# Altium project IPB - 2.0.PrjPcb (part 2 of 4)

## Sheet Mezzanine_Conn.SchDoc: MARS2 - IPB - Mezzanine Connector
size 431 x 279 mm; Organization: ORGANIZATION; Address1: APPLIED PHYSICS LAB; Address2: UNIVERSITY OF WASHINGTON; Address3: 1013 NE 40TH STREET; Address4: SEATTLE, WA 98105; Revision: -; SheetNumber: 3; SheetTotal: 23; ENG_APP_DATE: --/--/--; DSN_APP_DATE: --/--/--; CHK_APP_DATE: --/--/--
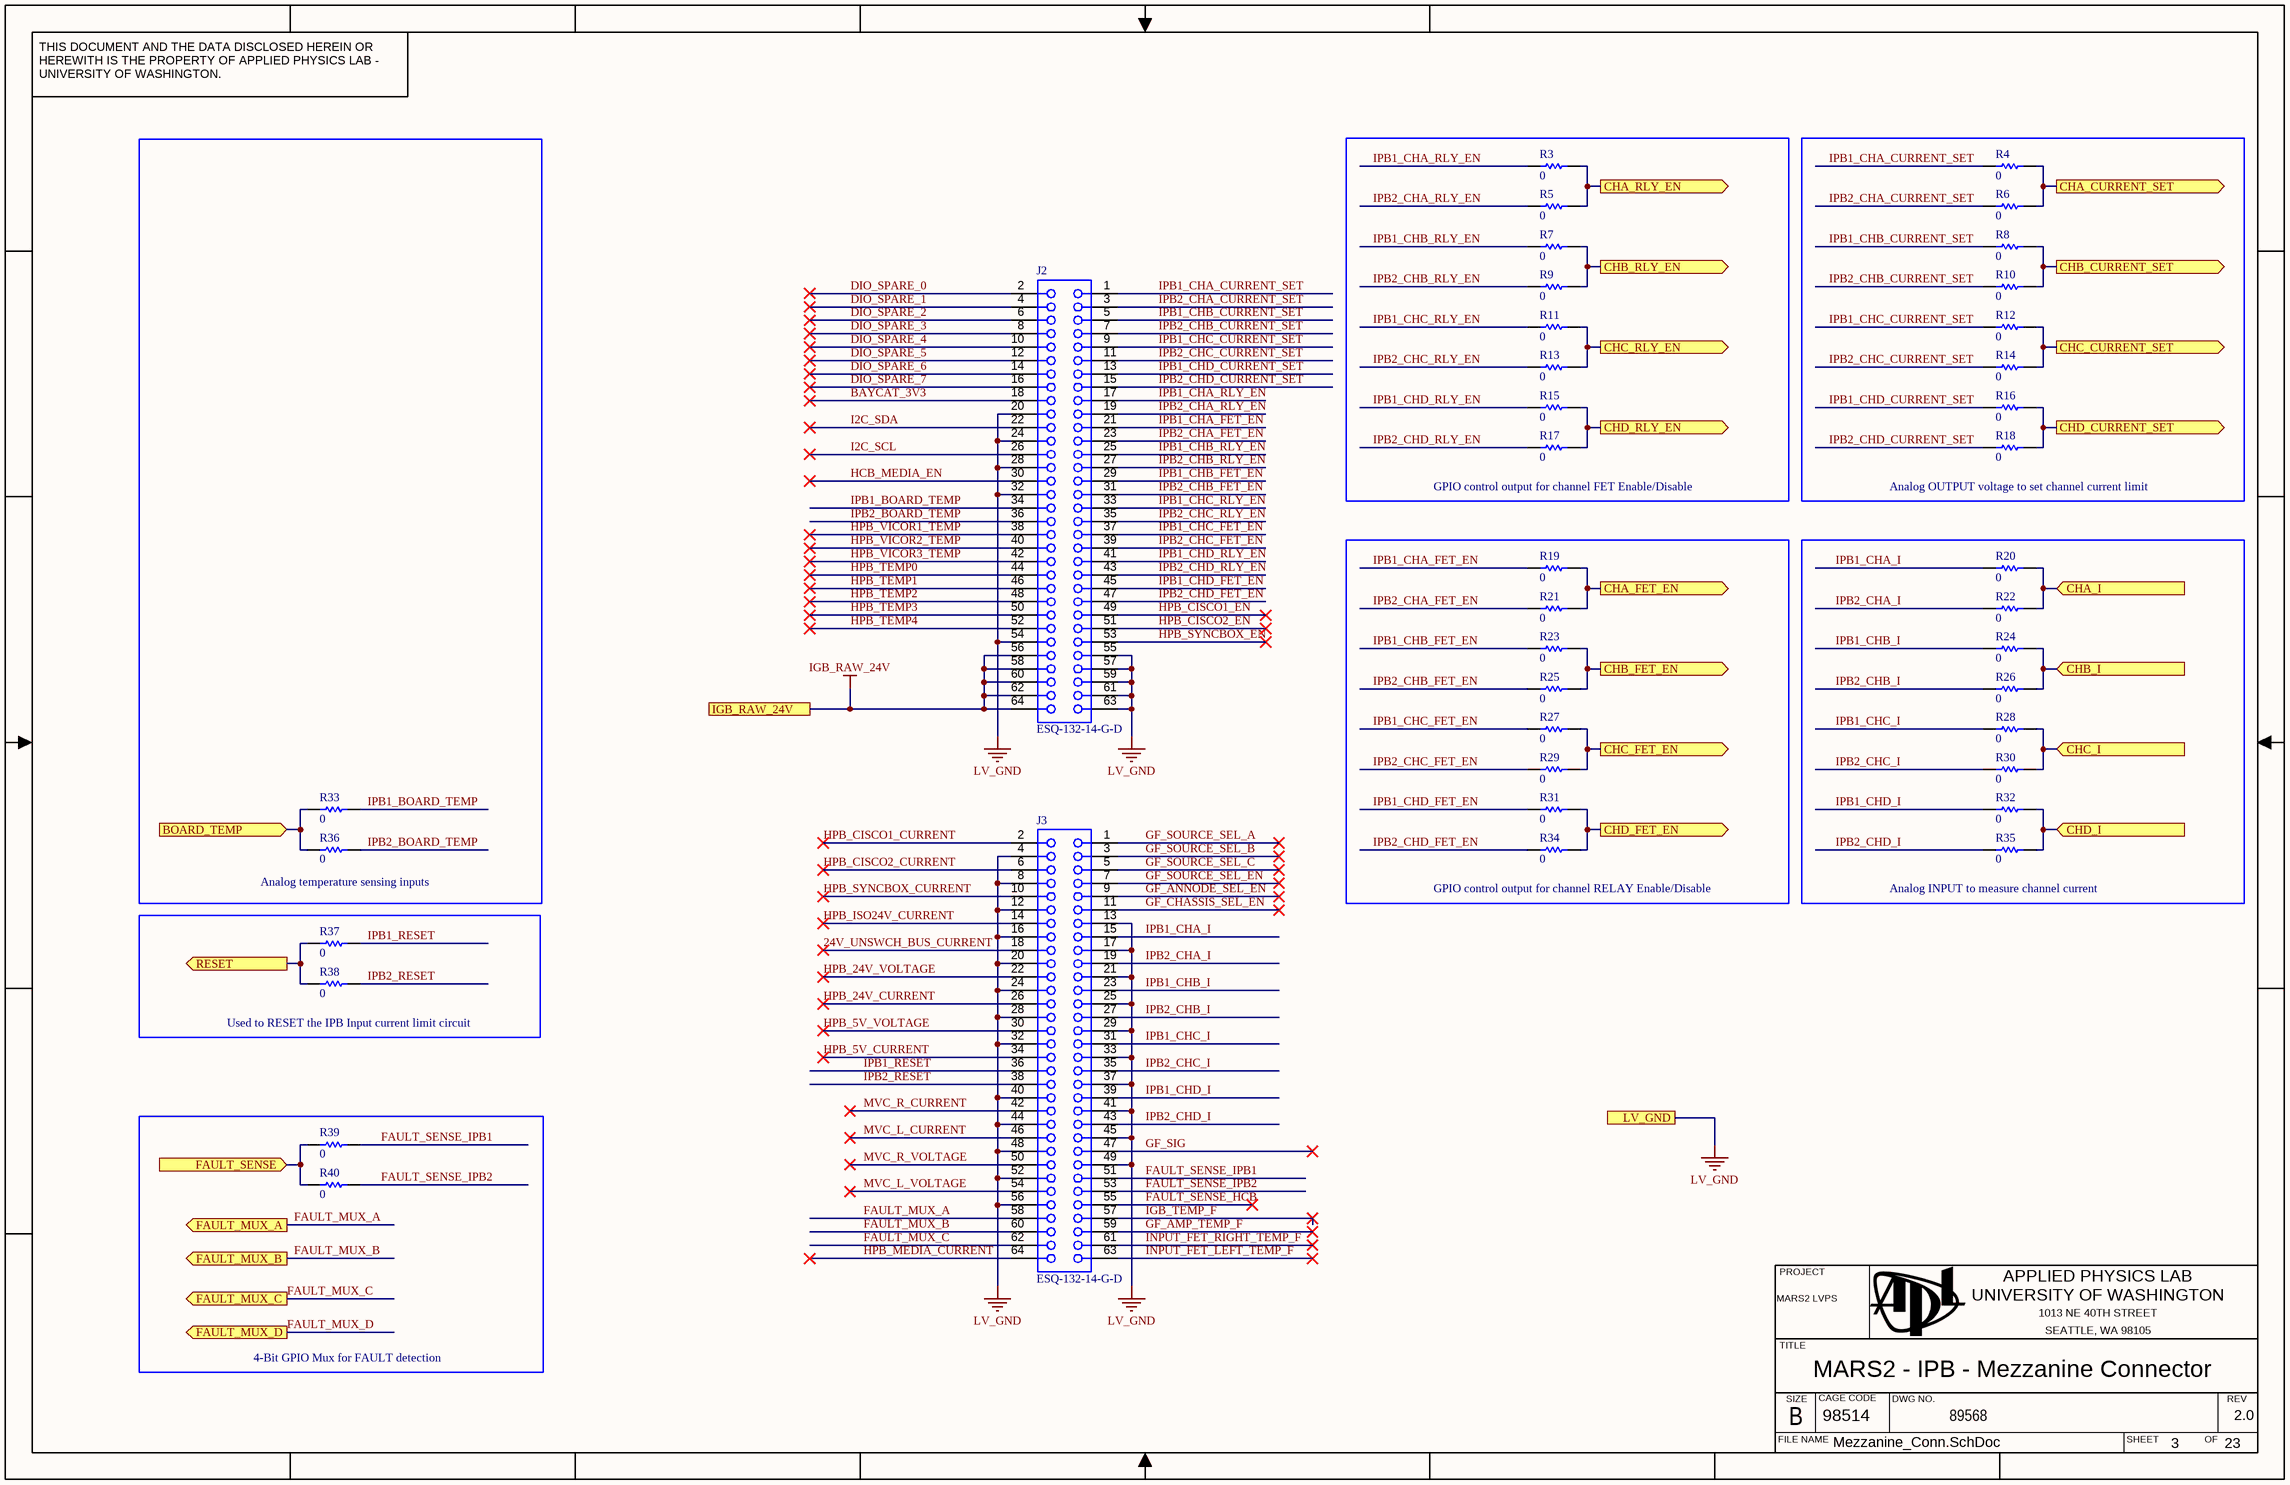
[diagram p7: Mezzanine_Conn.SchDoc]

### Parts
J2  ESQ-132-14-G-D  [SMTC-ESQ-132-14-X-D]
J3  ESQ-132-14-G-D  [SMTC-ESQ-132-14-X-D]
R3  value 0  [RESC2013X60X35ML10T20]  (hidden comment: Resistor 0R +/- 5% 0805 125 mW)
R4  value 0  [RESC2013X60X35ML10T20]  (hidden comment: Resistor 0R +/- 5% 0805 125 mW)
R5  value 0  [RESC2013X60X35ML10T20]  (hidden comment: Resistor 0R +/- 5% 0805 125 mW)
R6  value 0  [RESC2013X60X35ML10T20]  (hidden comment: Resistor 0R +/- 5% 0805 125 mW)
R7  value 0  [RESC2013X60X35ML10T20]  (hidden comment: Resistor 0R +/- 5% 0805 125 mW)
R8  value 0  [RESC2013X60X35ML10T20]  (hidden comment: Resistor 0R +/- 5% 0805 125 mW)
R9  value 0  [RESC2013X60X35ML10T20]  (hidden comment: Resistor 0R +/- 5% 0805 125 mW)
R10  value 0  [RESC2013X60X35ML10T20]  (hidden comment: Resistor 0R +/- 5% 0805 125 mW)
R11  value 0  [RESC2013X60X35ML10T20]  (hidden comment: Resistor 0R +/- 5% 0805 125 mW)
R12  value 0  [RESC2013X60X35ML10T20]  (hidden comment: Resistor 0R +/- 5% 0805 125 mW)
R13  value 0  [RESC2013X60X35ML10T20]  (hidden comment: Resistor 0R +/- 5% 0805 125 mW)
R14  value 0  [RESC2013X60X35ML10T20]  (hidden comment: Resistor 0R +/- 5% 0805 125 mW)
R15  value 0  [RESC2013X60X35ML10T20]  (hidden comment: Resistor 0R +/- 5% 0805 125 mW)
R16  value 0  [RESC2013X60X35ML10T20]  (hidden comment: Resistor 0R +/- 5% 0805 125 mW)
R17  value 0  [RESC2013X60X35ML10T20]  (hidden comment: Resistor 0R +/- 5% 0805 125 mW)
R18  value 0  [RESC2013X60X35ML10T20]  (hidden comment: Resistor 0R +/- 5% 0805 125 mW)
R19  value 0  [RESC2013X60X35ML10T20]  (hidden comment: Resistor 0R +/- 5% 0805 125 mW)
R20  value 0  [RESC2013X60X35ML10T20]  (hidden comment: Resistor 0R +/- 5% 0805 125 mW)
R21  value 0  [RESC2013X60X35ML10T20]  (hidden comment: Resistor 0R +/- 5% 0805 125 mW)
R22  value 0  [RESC2013X60X35ML10T20]  (hidden comment: Resistor 0R +/- 5% 0805 125 mW)
R23  value 0  [RESC2013X60X35ML10T20]  (hidden comment: Resistor 0R +/- 5% 0805 125 mW)
R24  value 0  [RESC2013X60X35ML10T20]  (hidden comment: Resistor 0R +/- 5% 0805 125 mW)
R25  value 0  [RESC2013X60X35ML10T20]  (hidden comment: Resistor 0R +/- 5% 0805 125 mW)
R26  value 0  [RESC2013X60X35ML10T20]  (hidden comment: Resistor 0R +/- 5% 0805 125 mW)
R27  value 0  [RESC2013X60X35ML10T20]  (hidden comment: Resistor 0R +/- 5% 0805 125 mW)
R28  value 0  [RESC2013X60X35ML10T20]  (hidden comment: Resistor 0R +/- 5% 0805 125 mW)
R29  value 0  [RESC2013X60X35ML10T20]  (hidden comment: Resistor 0R +/- 5% 0805 125 mW)
R30  value 0  [RESC2013X60X35ML10T20]  (hidden comment: Resistor 0R +/- 5% 0805 125 mW)
R31  value 0  [RESC2013X60X35ML10T20]  (hidden comment: Resistor 0R +/- 5% 0805 125 mW)
R32  value 0  [RESC2013X60X35ML10T20]  (hidden comment: Resistor 0R +/- 5% 0805 125 mW)
R33  value 0  [RESC2013X60X35ML10T20]  (hidden comment: Resistor 0R +/- 5% 0805 125 mW)
R34  value 0  [RESC2013X60X35ML10T20]  (hidden comment: Resistor 0R +/- 5% 0805 125 mW)
R35  value 0  [RESC2013X60X35ML10T20]  (hidden comment: Resistor 0R +/- 5% 0805 125 mW)
R36  value 0  [RESC2013X60X35ML10T20]  (hidden comment: Resistor 0R +/- 5% 0805 125 mW)
R37  value 0  [RESC2013X60X35ML10T20]  (hidden comment: Resistor 0R +/- 5% 0805 125 mW)
R38  value 0  [RESC2013X60X35ML10T20]  (hidden comment: Resistor 0R +/- 5% 0805 125 mW)
R39  value 0  [RESC2013X60X35ML10T20]  (hidden comment: Resistor 0R +/- 5% 0805 125 mW)
R40  value 0  [RESC2013X60X35ML10T20]  (hidden comment: Resistor 0R +/- 5% 0805 125 mW)

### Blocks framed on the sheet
Analog temperature sensing inputs: R33 R36
GPIO control output for channel FET Enable/Disable: R3 R5 R7 R9 R11 R13 R15 R17
Analog OUTPUT voltage to set channel current limit: R4 R6 R8 R10 R12 R14 R16 R18
GPIO control output for channel RELAY Enable/Disable: R19 R21 R23 R25 R27 R29 R31 R34
Analog INPUT to measure channel current: R20 R22 R24 R26 R28 R30 R32 R35
Used to RESET the IPB Input current limit circuit: R37 R38
4-Bit GPIO Mux for FAULT detection: R39 R40

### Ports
BOARD_TEMP (in), CHA_CURRENT_SET (out), CHA_FET_EN (out), CHA_I (in), CHA_RLY_EN (out), CHB_CURRENT_SET (out), CHB_FET_EN (out), CHB_I (in), CHB_RLY_EN (out), CHC_CURRENT_SET (out), CHC_FET_EN (out), CHC_I (in), CHC_RLY_EN (out), CHD_CURRENT_SET (out), CHD_FET_EN (out), CHD_I (in), CHD_RLY_EN (out), FAULT_MUX_A (out), FAULT_MUX_B (out), FAULT_MUX_C (out), FAULT_MUX_D (out), FAULT_SENSE (in), IGB_RAW_24V, LV_GND, RESET (out)

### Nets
IGB_RAW_24V: J2.56 J2.58 J2.60 J2.62 J2.64 ; port IGB_RAW_24V  [project net LV_IGB_P24V]
LV_GND: J2.20 J2.24 J2.28 J2.32 J2.54 J2.55 J2.57 J2.59 J2.61 J2.63 J3.4 J3.8 J3.12 J3.13 J3.16 J3.17 J3.20 J3.21 J3.24 J3.25 J3.28 J3.29 J3.32 J3.33 J3.37 J3.40 J3.41 J3.44 J3.45 J3.48 J3.49 J3.52 J3.56 ; port LV_GND
24V_UNSWCH_BUS_CURRENT: J3.18  [project net 24V_UNSWCH_BUS_CURRENT_3]
BAYCAT_3V3: J2.18  [project net BAYCAT_3V3_3]
BOARD_TEMP: R33.1 R36.1 ; port BOARD_TEMP
CHA_CURRENT_SET: R4.1 R6.1 ; port CHA_CURRENT_SET
CHA_FET_EN: R19.1 R21.1 ; port CHA_FET_EN
CHA_I: R20.1 R22.1 ; port CHA_I
CHA_RLY_EN: R3.1 R5.1 ; port CHA_RLY_EN
CHB_CURRENT_SET: R8.1 R10.1 ; port CHB_CURRENT_SET
CHB_FET_EN: R23.1 R25.1 ; port CHB_FET_EN
CHB_I: R24.1 R26.1 ; port CHB_I
CHB_RLY_EN: R7.1 R9.1 ; port CHB_RLY_EN
CHC_CURRENT_SET: R12.1 R14.1 ; port CHC_CURRENT_SET
CHC_FET_EN: R27.1 R29.1 ; port CHC_FET_EN
CHC_I: R28.1 R30.1 ; port CHC_I
CHC_RLY_EN: R11.1 R13.1 ; port CHC_RLY_EN
CHD_CURRENT_SET: R16.1 R18.1 ; port CHD_CURRENT_SET
CHD_FET_EN: R31.1 R34.1 ; port CHD_FET_EN
CHD_I: R32.1 R35.1 ; port CHD_I
CHD_RLY_EN: R15.1 R17.1 ; port CHD_RLY_EN
DIO_SPARE_0: J2.2  [project net DIO_SPARE_0_3]
DIO_SPARE_1: J2.4  [project net DIO_SPARE_1_3]
DIO_SPARE_2: J2.6  [project net DIO_SPARE_2_3]
DIO_SPARE_3: J2.8  [project net DIO_SPARE_3_3]
DIO_SPARE_4: J2.10  [project net DIO_SPARE_4_3]
DIO_SPARE_5: J2.12  [project net DIO_SPARE_5_3]
DIO_SPARE_6: J2.14  [project net DIO_SPARE_6_3]
DIO_SPARE_7: J2.16  [project net DIO_SPARE_7_3]
FAULT_MUX_A: J3.58 ; port FAULT_MUX_A
FAULT_MUX_B: J3.60 ; port FAULT_MUX_B
FAULT_MUX_C: J3.62 ; port FAULT_MUX_C
FAULT_SENSE: R39.1 R40.1 ; port FAULT_SENSE
FAULT_SENSE_HCB: J3.55  [project net FAULT_SENSE_HCB_3]
FAULT_SENSE_IPB1: J3.51 R39.2  [project net FAULT_SENSE_IPB1_3]
FAULT_SENSE_IPB2: J3.53 R40.2  [project net FAULT_SENSE_IPB2_3]
GF_AMP_TEMP_F: J3.59  [project net GF_AMP_TEMP_F_3]
GF_ANNODE_SEL_EN: J3.9  [project net GF_ANNODE_SEL_EN_3]
GF_CHASSIS_SEL_EN: J3.11  [project net GF_CHASSIS_SEL_EN_3]
GF_SIG: J3.47  [project net GF_SIG_3]
GF_SOURCE_SEL_A: J3.1  [project net GF_SOURCE_SEL_A_3]
GF_SOURCE_SEL_B: J3.3  [project net GF_SOURCE_SEL_B_3]
GF_SOURCE_SEL_C: J3.5  [project net GF_SOURCE_SEL_C_3]
GF_SOURCE_SEL_EN: J3.7  [project net GF_SOURCE_SEL_EN_3]
HCB_MEDIA_EN: J2.30  [project net HCB_MEDIA_EN_3]
HPB_5V_CURRENT: J3.34  [project net HPB_5V_CURRENT_3]
HPB_5V_VOLTAGE: J3.30  [project net HPB_5V_VOLTAGE_3]
HPB_24V_CURRENT: J3.26  [project net HPB_24V_CURRENT_3]
HPB_24V_VOLTAGE: J3.22  [project net HPB_24V_VOLTAGE_3]
HPB_CISCO1_CURRENT: J3.2  [project net HPB_CISCO1_CURRENT_3]
HPB_CISCO1_EN: J2.49  [project net HPB_CISCO1_EN_3]
HPB_CISCO2_CURRENT: J3.6  [project net HPB_CISCO2_CURRENT_3]
HPB_CISCO2_EN: J2.51  [project net HPB_CISCO2_EN_3]
HPB_ISO24V_CURRENT: J3.14  [project net HPB_ISO24V_CURRENT_3]
HPB_MEDIA_CURRENT: J3.64  [project net HPB_MEDIA_CURRENT_3]
HPB_SYNCBOX_CURRENT: J3.10  [project net HPB_SYNCBOX_CURRENT_3]
HPB_SYNCBOX_EN: J2.53  [project net HPB_SYNCBOX_EN_3]
HPB_TEMP0: J2.44  [project net HPB_TEMP0_3]
HPB_TEMP1: J2.46  [project net HPB_TEMP1_3]
HPB_TEMP2: J2.48  [project net HPB_TEMP2_3]
HPB_TEMP3: J2.50  [project net HPB_TEMP3_3]
HPB_TEMP4: J2.52  [project net HPB_TEMP4_3]
HPB_VICOR1_TEMP: J2.38  [project net HPB_VICOR1_TEMP_3]
HPB_VICOR2_TEMP: J2.40  [project net HPB_VICOR2_TEMP_3]
HPB_VICOR3_TEMP: J2.42  [project net HPB_VICOR3_TEMP_3]
I2C_SCL: J2.26  [project net I2C_SCL_3]
I2C_SDA: J2.22  [project net I2C_SDA_3]
IGB_TEMP_F: J3.57  [project net IGB_TEMP_F_3]
INPUT-FAULT-RESET: R37.1 R38.1 ; port RESET
INPUT_FET_LEFT_TEMP_F: J3.63  [project net INPUT_FET_LEFT_TEMP_F_3]
INPUT_FET_RIGHT_TEMP_F: J3.61  [project net INPUT_FET_RIGHT_TEMP_F_3]
IPB1_BOARD_TEMP: J2.34 R33.2  [project net IPB1_BOARD_TEMP_3]
IPB1_CHA_CURRENT_SET: J2.1 R4.2  [project net IPB1_CHA_CURRENT_SET_3]
IPB1_CHA_FET_EN: J2.21 R19.2  [project net IPB1_CHA_FET_EN_3]
IPB1_CHA_I: J3.15 R20.2  [project net IPB1_CHA_I_3]
IPB1_CHA_RLY_EN: J2.17 R3.2  [project net IPB1_CHA_RLY_EN_3]
IPB1_CHB_CURRENT_SET: J2.5 R8.2  [project net IPB1_CHB_CURRENT_SET_3]
IPB1_CHB_FET_EN: J2.29 R23.2  [project net IPB1_CHB_FET_EN_3]
IPB1_CHB_I: J3.23 R24.2  [project net IPB1_CHB_I_3]
IPB1_CHB_RLY_EN: J2.25 R7.2  [project net IPB1_CHB_RLY_EN_3]
IPB1_CHC_CURRENT_SET: J2.9 R12.2  [project net IPB1_CHC_CURRENT_SET_3]
IPB1_CHC_FET_EN: J2.37 R27.2  [project net IPB1_CHC_FET_EN_3]
IPB1_CHC_I: J3.31 R28.2  [project net IPB1_CHC_I_3]
IPB1_CHC_RLY_EN: J2.33 R11.2  [project net IPB1_CHC_RLY_EN_3]
IPB1_CHD_CURRENT_SET: J2.13 R16.2  [project net IPB1_CHD_CURRENT_SET_3]
IPB1_CHD_FET_EN: J2.45 R31.2  [project net IPB1_CHD_FET_EN_3]
IPB1_CHD_I: J3.39 R32.2  [project net IPB1_CHD_I_3]
IPB1_CHD_RLY_EN: J2.41 R15.2  [project net IPB1_CHD_RLY_EN_3]
IPB1_RESET: J3.36 R37.2  [project net IPB1_RESET_3]
IPB2_BOARD_TEMP: J2.36 R36.2  [project net IPB2_BOARD_TEMP_3]
IPB2_CHA_CURRENT_SET: J2.3 R6.2  [project net IPB2_CHA_CURRENT_SET_3]
IPB2_CHA_FET_EN: J2.23 R21.2  [project net IPB2_CHA_FET_EN_3]
IPB2_CHA_I: J3.19 R22.2  [project net IPB2_CHA_I_3]
IPB2_CHA_RLY_EN: J2.19 R5.2  [project net IPB2_CHA_RLY_EN_3]
IPB2_CHB_CURRENT_SET: J2.7 R10.2  [project net IPB2_CHB_CURRENT_SET_3]
IPB2_CHB_FET_EN: J2.31 R25.2  [project net IPB2_CHB_FET_EN_3]
IPB2_CHB_I: J3.27 R26.2  [project net IPB2_CHB_I_3]
IPB2_CHB_RLY_EN: J2.27 R9.2  [project net IPB2_CHB_RLY_EN_3]
IPB2_CHC_CURRENT_SET: J2.11 R14.2  [project net IPB2_CHC_CURRENT_SET_3]
IPB2_CHC_FET_EN: J2.39 R29.2  [project net IPB2_CHC_FET_EN_3]
IPB2_CHC_I: J3.35 R30.2  [project net IPB2_CHC_I_3]
IPB2_CHC_RLY_EN: J2.35 R13.2  [project net IPB2_CHC_RLY_EN_3]
IPB2_CHD_CURRENT_SET: J2.15 R18.2  [project net IPB2_CHD_CURRENT_SET_3]
IPB2_CHD_FET_EN: J2.47 R34.2  [project net IPB2_CHD_FET_EN_3]
IPB2_CHD_I: J3.43 R35.2  [project net IPB2_CHD_I_3]
IPB2_CHD_RLY_EN: J2.43 R17.2  [project net IPB2_CHD_RLY_EN_3]
IPB2_RESET: J3.38 R38.2  [project net IPB2_RESET_3]
MVC_L_CURRENT: J3.46  [project net MVC_L_CURRENT_3]
MVC_L_VOLTAGE: J3.54  [project net MVC_L_VOLTAGE_3]
MVC_R_CURRENT: J3.42  [project net MVC_R_CURRENT_3]
MVC_R_VOLTAGE: J3.50  [project net MVC_R_VOLTAGE_3]

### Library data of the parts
J2 J3 = CMP-002-00093-5: Conn Elevated Socket SKT 64 POS 2.54mm Solder ST Top Entry Thru-Hole Tube; Manufacturer: Samtec; Voltage Rating (AC): 550V; Current Rating: 6.9A; Number of Contacts: 64; Row Spacing: 0.1inch; Connector Type: Receptacle; Contact Resistance: 10mR
R3-R40 = CMP-009-00007-7: Chip Resistor, 0 Ohm, 0.125 W, -55 to 155 degC, 0805 (2012 Metric); Power: 125mW; Voltage Rating: 50V

## Sheet External_Interface_Conn.SchDoc: MARS2 - IPB - Instrument Channel Conn
size 431 x 279 mm; Organization: ORGANIZATION; Address1: APPLIED PHYSICS LAB; Address2: UNIVERSITY OF WASHINGTON; Address3: 1013 NE 40TH STREET; Address4: SEATTLE, WA 98105; Revision: -; SheetNumber: 9; SheetTotal: 23; ENG_APP_DATE: --/--/--; DSN_APP_DATE: --/--/--; CHK_APP_DATE: --/--/--
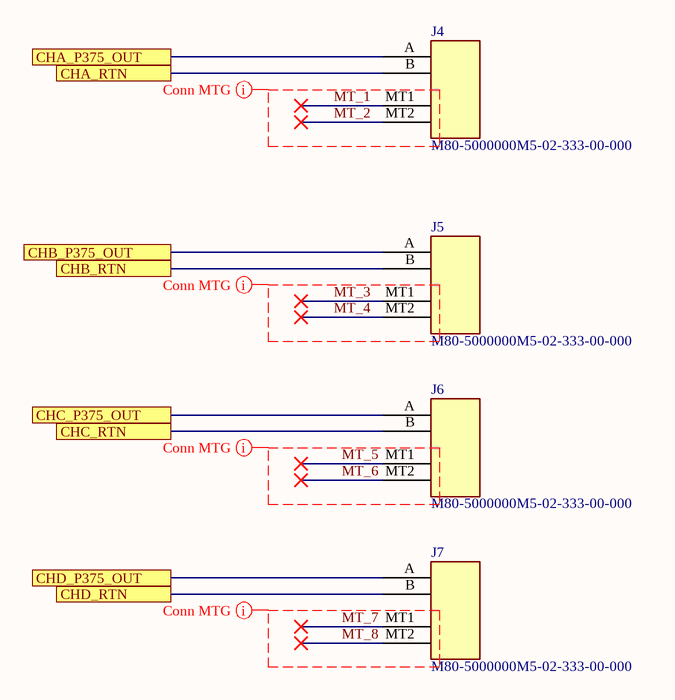
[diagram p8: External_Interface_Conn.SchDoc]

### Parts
J4  M80-5000000M5-02-333-00-000  [FP-M80-5000000M5-02-333-0-MFG]
J5  M80-5000000M5-02-333-00-000  [FP-M80-5000000M5-02-333-0-MFG]
J6  M80-5000000M5-02-333-00-000  [FP-M80-5000000M5-02-333-0-MFG]
J7  M80-5000000M5-02-333-00-000  [FP-M80-5000000M5-02-333-0-MFG]

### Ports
CHA_P375_OUT, CHA_RTN, CHB_P375_OUT, CHB_RTN, CHC_P375_OUT, CHC_RTN, CHD_P375_OUT, CHD_RTN

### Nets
MT_1: J4.MT1(MNT_1)  [project net MT_1_9]
MT_2: J4.MT2(MNT_2)  [project net MT_2_9]
MT_3: J5.MT1(MNT_1)  [project net MT_3_9]
MT_4: J5.MT2(MNT_2)  [project net MT_4_9]
MT_5: J6.MT1(MNT_1)  [project net MT_5_9]
MT_6: J6.MT2(MNT_2)  [project net MT_6_9]
MT_7: J7.MT1(MNT_1)  [project net MT_7_9]
MT_8: J7.MT2(MNT_2)  [project net MT_8_9]
NetD1_A_1: J4.B ; port CHA_RTN
NetD1_A_4: J4.A ; port CHA_P375_OUT
NetD1_B_1: J5.B ; port CHB_RTN
NetD1_B_4: J5.A ; port CHB_P375_OUT
NetD1_C_1: J6.B ; port CHC_RTN
NetD1_C_4: J6.A ; port CHC_P375_OUT
NetD1_D_1: J7.B ; port CHD_RTN
NetD1_D_4: J7.A ; port CHD_P375_OUT

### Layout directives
net class Mounting Hole: MT_1, MT_2, MT_3, MT_4, MT_5, MT_6, MT_7, MT_8

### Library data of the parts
J4-J7 = CMP-002-00075-7: Conn Header R/a 2POS 4MM; Manufacturer: Harwin; Number of Positions: 2; Pitch: 4.00mm; Current Rating: 40A; Contact Resistance: 25mR; Voltage Rating: 800V; Gender: Male; Insulation Resistance: 100MR

## Sheet Fault_Sensing.SchDoc: MARS2 - IPB - Fault Multiplexing
size 431 x 279 mm; Organization: ORGANIZATION; Address1: APPLIED PHYSICS LAB; Address2: UNIVERSITY OF WASHINGTON; Address3: 1013 NE 40TH STREET; Address4: SEATTLE, WA 98105; Revision: -; SheetNumber: 10; SheetTotal: 23; ENG_APP_DATE: --/--/--; DSN_APP_DATE: --/--/--; CHK_APP_DATE: --/--/--
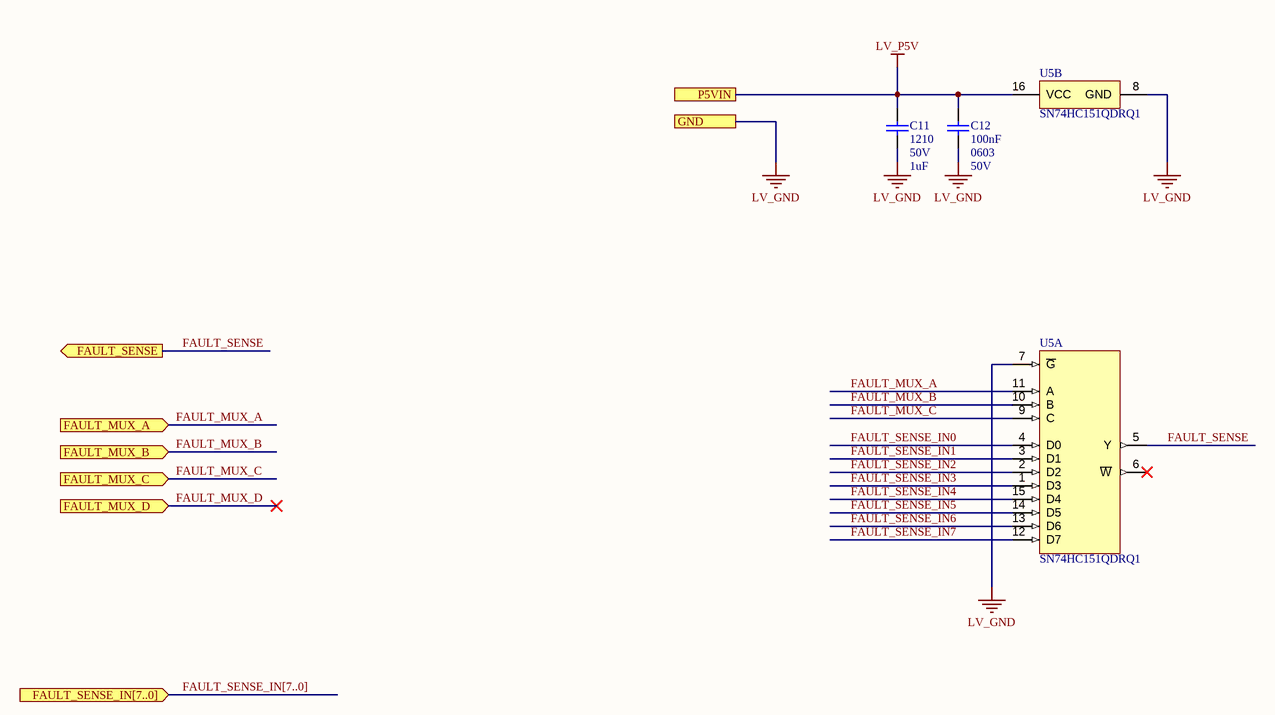
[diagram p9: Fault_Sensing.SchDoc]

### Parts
C11  value 1uF  Case/Package: 1210  Voltage Rating: 50V  [CAPC3225X270X30ML30]  (hidden comment: Capacitor 1uF 10%, 50V, X7R, 1210)
C12  value 100nF  Case/Package: 0603  Voltage Rating: 50V  [CAPC1608X90X40ML10T20]  (hidden comment: Capacitor 100nF +/- 10%, 50V, X7R, 0603)
U5  SN74HC151QDRQ1  [D0016A_M]  (parts A,B of 2)

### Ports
FAULT_MUX_A (in), FAULT_MUX_B (in), FAULT_MUX_C (in), FAULT_MUX_D (in), FAULT_SENSE (out), FAULT_SENSE_IN[7..0] (in), GND, P5VIN

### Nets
LV_GND: C11.2 C12.1 U5.7(~{G}) U5.8(GND) ; port GND
LV_P5V: C11.1 C12.2 U5.16(VCC) ; port P5VIN
FAULT_MUX_A: U5.11(A) ; port FAULT_MUX_A
FAULT_MUX_B: U5.10(B) ; port FAULT_MUX_B
FAULT_MUX_C: U5.9(C) ; port FAULT_MUX_C
FAULT_SENSE: U5.5(Y) ; port FAULT_SENSE
FAULT_SENSE_IN0: U5.4(D0)
FAULT_SENSE_IN1: U5.3(D1)
FAULT_SENSE_IN2: U5.2(D2)
FAULT_SENSE_IN3: U5.1(D3)
FAULT_SENSE_IN4: U5.15(D4)
FAULT_SENSE_IN5: U5.14(D5)
FAULT_SENSE_IN6: U5.13(D6)
FAULT_SENSE_IN7: U5.12(D7)

Not connected (* = marked no-connect by the designer): U5 6(~{W})*

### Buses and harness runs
bus FAULT_SENSE_IN[7..0] = port FAULT_SENSE_IN[7..0]

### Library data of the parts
C11 = CMP-001-00181-10: Chip Capacitor, 1uF, 10%, 50 V, X7R 1210 (3225 Metric); Capacitor Type: Ceramic
C12 = CMP-001-00206-10: Chip Capacitor, 100nF, +/- 10%, 50 V, X7R 0603 (1608 Metric); Capacitor Type: Ceramic
U5 = CMP-016-00018-2: Automotive 5-V, 8: 1 1-channel general-purpose multiplexer 16-SOIC -40 to 125; Max Supply Voltage: 6V; Bandwidth: 28MHz; Min Supply Voltage: 2V; Number of Output Lines: 1; Number of Input Lines: 8; High Level Output Current: 7.8mA; Logic Function: Multiplexer,Mux; Propagation Delay: 33ns

## Sheet Local_Power_Supplies.SchDoc: MARS2 - IPB - Local Power Supplies
size 431 x 279 mm; Organization: ORGANIZATION; Address1: APPLIED PHYSICS LAB; Address2: UNIVERSITY OF WASHINGTON; Address3: 1013 NE 40TH STREET; Address4: SEATTLE, WA 98105; Revision: -; SheetNumber: 11; SheetTotal: 23; ENG_APP_DATE: --/--/--; DSN_APP_DATE: --/--/--; CHK_APP_DATE: --/--/--
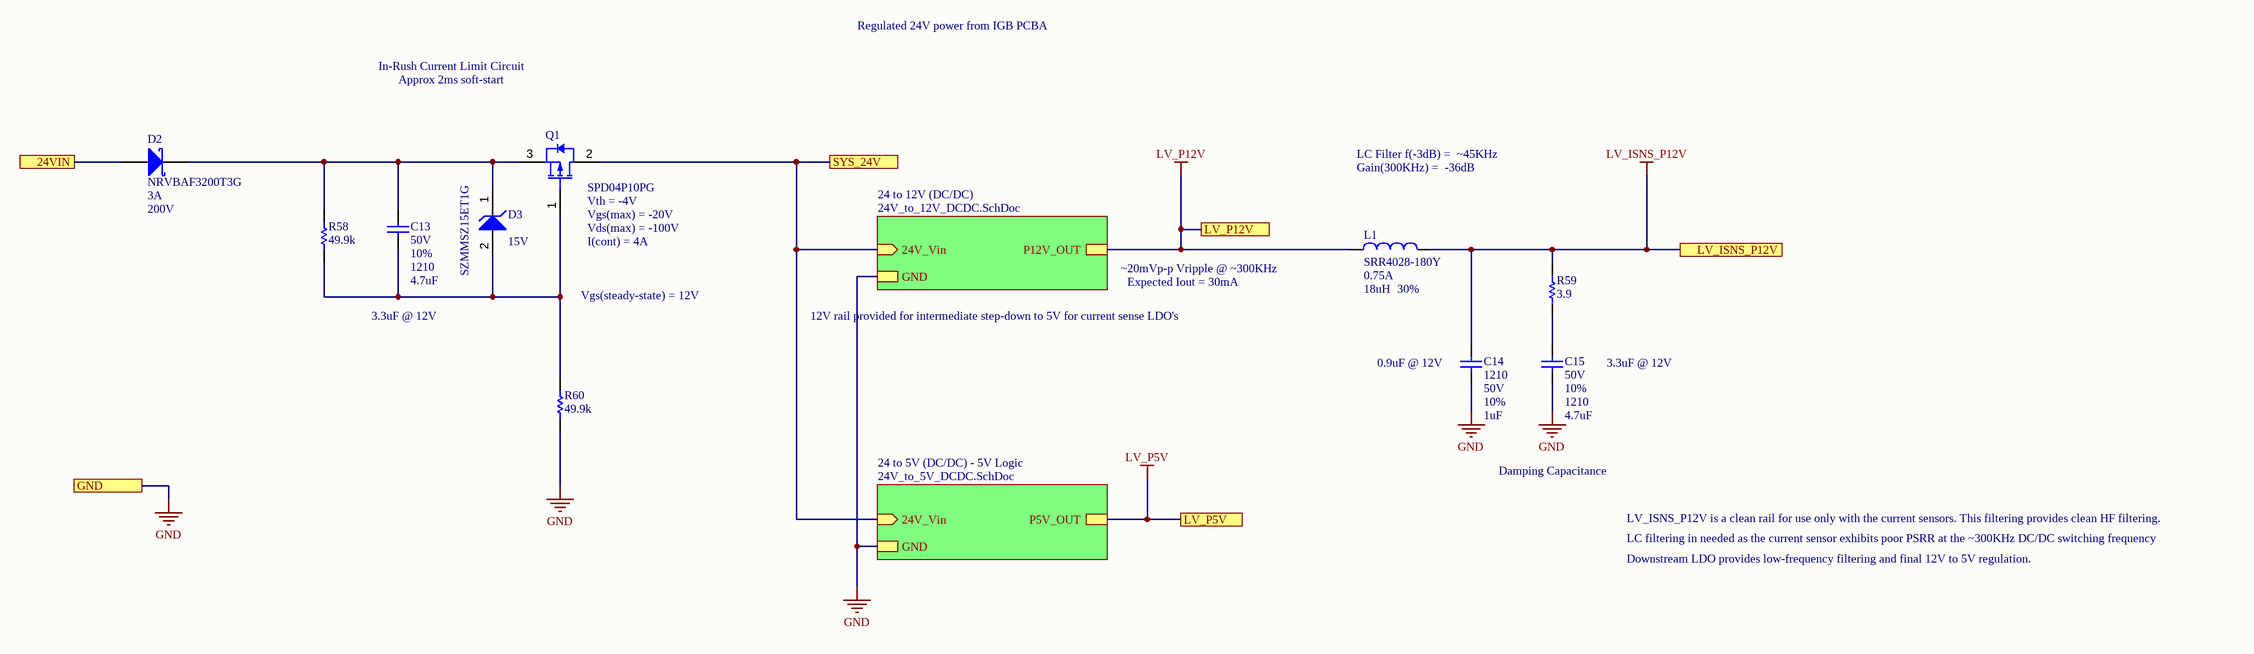
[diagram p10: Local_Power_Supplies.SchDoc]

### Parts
C13  value 4.7uF  Voltage Rating: 50V  Tolerance: 10%  Case/Package: 1210  [CAPC3225X270X30ML30]  (hidden comment: Capacitor 4.7uF 10%, 50V, X7R, 1210)
C14  value 1uF  Case/Package: 1210  Voltage Rating: 50V  Tolerance: 10%  [CAPC3225X270X30ML30]  (hidden comment: Capacitor 1uF 10%, 50V, X7R, 1210)
C15  value 4.7uF  Voltage Rating: 50V  Tolerance: 10%  Case/Package: 1210  [CAPC3225X270X30ML30]  (hidden comment: Capacitor 4.7uF 10%, 50V, X7R, 1210)
D2  NRVBAF3200T3G  Average Rectified Current: 3A  Max Reverse Voltage (DC): 200V  [DIOM4326X11M]
D3  SZMMSZ15ET1G  Zener Voltage: 15V  [ONSC-SOD-123-2-425-04_V]
L1  SRR4028-180Y  Inductance Tolerance: 30%  Saturation Current: 0.75A  Inductance: 18uH  [INDP4848X30M]
Q1  SPD04P10PG  [INF-PG-TO252-3-1_M]
R58  value 49.9k  [RESC1608X55X25ML10T15]  (hidden comment: Resistor 49K9 +/-1% 0603 100 mW)
R59  value 3.9  [RESC1609X50X30ML08T20]  (hidden comment: Resistor 3R9 +/-1% 0603 100 mW)
R60  value 49.9k  [RESC1608X55X25ML10T15]  (hidden comment: Resistor 49K9 +/-1% 0603 100 mW)

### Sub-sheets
24 to 5V (DC/DC) - 5V Logic = 24V_to_5V_DCDC.SchDoc: 24V_Vin (in), P5V_OUT, GND
24 to 12V (DC/DC) = 24V_to_12V_DCDC.SchDoc: 24V_Vin (in), P12V_OUT, GND

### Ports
24VIN, GND, LV_ISNS_P12V, LV_P5V, LV_P12V, SYS_24V

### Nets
COIL_DRV_HIGH: Q1.2(DRAIN) ; port SYS_24V, sheet 24 to 12V (DC/DC)/24V_Vin, sheet 24 to 5V (DC/DC) - 5V Logic/24V_Vin
GND: C14.2 C15.2 R60.1 ; port GND, sheet 24 to 12V (DC/DC)/GND, sheet 24 to 5V (DC/DC) - 5V Logic/GND  [project net LV_GND]
LV_IGB_P24V: D2.1(A) ; port 24VIN
LV_ISNS_P12V: C14.1 L1.2 R59.2 ; port LV_ISNS_P12V
LV_P5V: port LV_P5V, sheet 24 to 5V (DC/DC) - 5V Logic/P5V_OUT
LV_P12V: L1.1 ; port LV_P12V, sheet 24 to 12V (DC/DC)/P12V_OUT
NetC13_1: C13.1 D3.2(A) Q1.1(GATE) R58.1 R60.2
NetC13_2: C13.2 D2.2(K) D3.1(K) Q1.3(SOURCE) R58.2
NetC15_1: C15.1 R59.1

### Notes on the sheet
- Regulated 24V power from IGB PCBA
- In-Rush Current Limit Circuit
- Approx 2ms soft-start
- LC Filter f(-3dB) =  ~45KHz
- Gain(300KHz) =  -36dB
- (near Q1) Vgs(max) = -20V
- (near Q1) Vds(max) = -100V
- (near Q1) I(cont) = 4A
- (near Q1) Vth = -4V
- 3.3uF @ 12V
- Vgs(steady-state) = 12V
- 12V rail provided for intermediate step-down to 5V for current sense LDO's
- |0mVp-p Vripple @ ~300KHz
- Expected Iout = 30mA
- (near C14) 0.9uF @ 12V
- Damping Capacitance
- LV_ISNS_P12V is a clean rail for use only with the current sensors. This filtering provides clean HF filtering.
- Downstream LDO provides low-frequency filtering and final 12V to 5V regulation.
- LC filtering in needed as the current sensor exhibits poor PSRR at the ~300KHz DC/DC switching frequency

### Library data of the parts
C13 C15 = CMP-001-00183-10: Chip Capacitor, 4.7uF, 10%, 50 V, X7R 1210 (3225 Metric); Capacitor Type: Ceramic; Decade: 1uF
C14 = CMP-001-00181-10: as C11 on sheet Fault_Sensing
D2 = CMP-004-00041-1: Diode Schottky Barrier Rectifier 200V 3A 2-Pin SMA-FL T/R
D3 = CMP-004-00039-2: Diode Zener Single 15V 5% 500mW Automotive 2-Pin SOD-123 T/R; Max Reverse Leakage Current: 50nA
L1 = CMP-006-00041-3: Inductor Power Shielded Wirewound 18uH 30% 11.64 Q-Factor Ferrite 0.75A Saturation 160mROhm DCR; Manufacturer: Bourns; Q Factor: 11.64; Self Resonant Frequency: 25MHz; Current Rating: 0.98A; Decade: 10uH; DC Resistance (DCR): 160mR
Q1 = CMP-013-00049-3: Trans MOSFET P-CH 100V 4A Automotive 3-Pin(2+Tab) TO-252 T/R; Input Capacitance: 319pF; Drain to Source Breakdown Voltage: -100V; Rds On Max: 1R; Power Dissipation: 38W; Gate to Source Voltage (Vgs): 20V; Transistor Type: PMOS
R58 R60 = CMP-009-01001-4: Chip Resistor, 49.9k Ohm, +/- 1%, 0.1 W, -55 to 155 degC, 0603 (1608 Metric); Power: 100mW; Voltage Rating: 75V; Decade: 10k
R59 = CMP-009-01177-2: Chip Resistor, 3.9 Ohm, +/- 1%, 0.1 W, -55 to 155 degC, 0603 (1608 Metric); Voltage Rating: SEE DATASHEET; Power: 100mW; Decade: 1

## Sheet 24V_to_12V_DCDC.SchDoc: MARS2 - IPB - 24V to 12V DC/DC
size 431 x 279 mm; SheetNumber: 13; SheetTotal: 23; ENG_APP_DATE: --/--/--; DSN_APP_DATE: --/--/--; CHK_APP_DATE: --/--/--
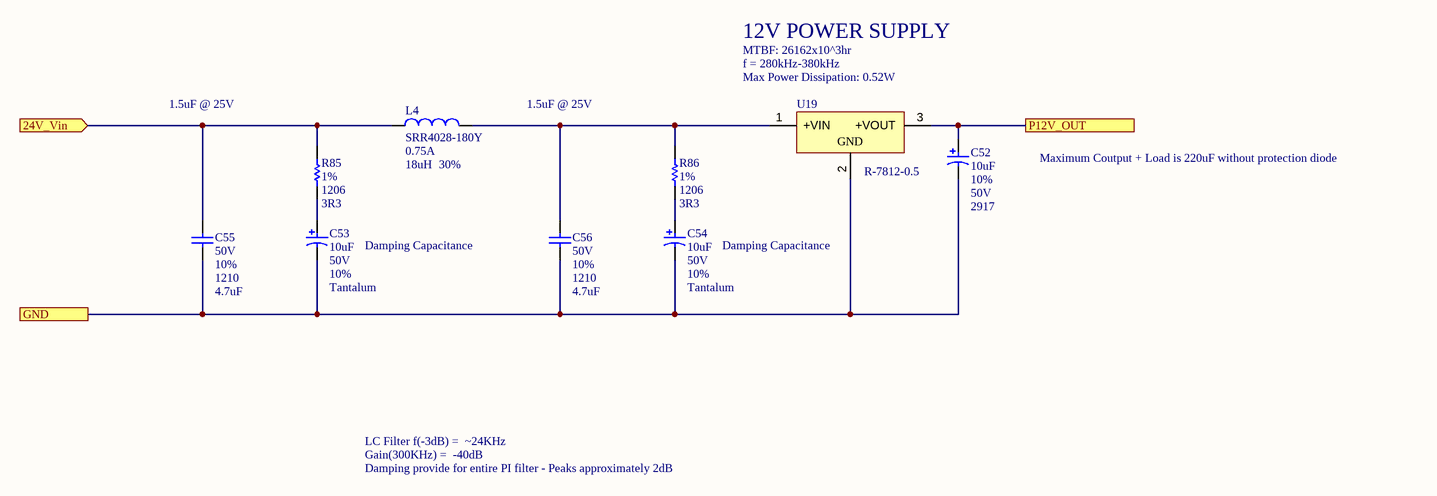
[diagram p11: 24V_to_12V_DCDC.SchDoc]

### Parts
C52  value 10uF  Tolerance: 10%  Voltage Rating: 50V  Case/Package: 2917  [KEMT-D-7343-31-2_L]  (hidden comment: T491D106K050AT)
C53  value 10uF  Voltage: 50V  Tolerance: 10%  Dielectric Material: Tantalum  [KEMT-D-7343-31-2_L]  (hidden comment: T491D106K050AT)
C54  value 10uF  Voltage: 50V  Tolerance: 10%  Dielectric Material: Tantalum  [KEMT-D-7343-31-2_L]  (hidden comment: T491D106K050AT)
C55  value 4.7uF  Voltage Rating: 50V  Tolerance: 10%  Case/Package: 1210  [CAPC3225X270X30ML30]  (hidden comment: Capacitor 4.7uF 10%, 50V, X7R, 1210)
C56  value 4.7uF  Voltage Rating: 50V  Tolerance: 10%  Case/Package: 1210  [CAPC3225X270X30ML30]  (hidden comment: Capacitor 4.7uF 10%, 50V, X7R, 1210)
L4  SRR4028-180Y  Inductance Tolerance: 30%  Saturation Current: 0.75A  Inductance: 18uH  [INDP4848X30M]
R85  value 3R3  Tolerance: 1%  Case/Package: 1206  [RESC3115X07M]  (hidden comment: Res Thick Film 1206 3.3 Ohm 1% 0.5W ±200ppm/°C Molded SMD Punched Carrier T/R)
R86  value 3R3  Tolerance: 1%  Case/Package: 1206  [RESC3115X07M]  (hidden comment: Res Thick Film 1206 3.3 Ohm 1% 0.5W ±200ppm/°C Molded SMD Punched Carrier T/R)
U19  R-7812-0.5  [REPO-R-78XX-3_V]

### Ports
24V_Vin (in), GND, P12V_OUT

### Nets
COIL_DRV_HIGH: C55.2 L4.1 R85.2 ; port 24V_Vin
LV_GND: C52.2 C53.2 C54.2 C55.1 C56.1 U19.2(GND) ; port GND
LV_P12V: C52.1 U19.3(+VOUT) ; port P12V_OUT
NetC53_1: C53.1 R85.1
NetC54_1: C54.1 R86.1
NetC56_2: C56.2 L4.2 R86.2 U19.1(+VIN)

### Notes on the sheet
- 12V POWER SUPPLY
- MTBF: 26162x10^3hr
- f = 280kHz-380kHz
- (near U19) Max Power Dissipation: 0.52W
- 1.5uF @ 25V
- Maximum Coutput + Load is 220uF without protection diode
- Damping Capacitance
- LC Filter f(-3dB) =  |4KHz
- Gain(300KHz) =  -40dB
- Damping provide for entire PI filter - Peaks approximately 2dB

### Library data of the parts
C52-C54 = CMP-001-00088-10: 10uF Solid MnO2 Tantalum Electrolytic Capacitor; 50 V dc +/-10%; T491 Series; Manufacturer: KEMET; Life (Hours): 2000Hour; Dissipation Factor: 6%; Ripple Current: 433mA; Leakage Current: 5uA; ESR (Equivalent Series Resistance): 800mR; Polarity: Polar
C55 C56 = CMP-001-00183-10: as C13 on sheet Local_Power_Supplies
L4 = CMP-006-00041-3: as L1 on sheet Local_Power_Supplies
R85 R86 = CMP-009-01213-6: Chip Resistor, 3.3 Ohm, 1%, 0.5W, ±200ppm/°C, 1206 (3216 Metric); Manufacturer: Panasonic; Power: 500mW; Decade: 1
U19 = CMP-019-00064-2: 0.5A DC/DC-Converter 'INNOLINE' SIP3 reg; V. In: 15-32; V. Out: 12; mA. Out: 500; Current - Output 1: 500mA; Isolation Voltage: 1kV; Min Input Voltage: 15V; Switching Frequency: 380kHz; Efficiency: 97%; Max Input Voltage: 32V; Max Output Voltage: 12V; Max Output Power: 6W; Nominal Input Voltage: 24V; Isolation: Non-Isolated

## Sheet 24V_to_5V_DCDC.SchDoc: MARS2 - IPB - 24V to 5V DC/DC
size 431 x 279 mm; SheetNumber: 12; SheetTotal: 23; ENG_APP_DATE: --/--/--; DSN_APP_DATE: --/--/--; CHK_APP_DATE: --/--/--
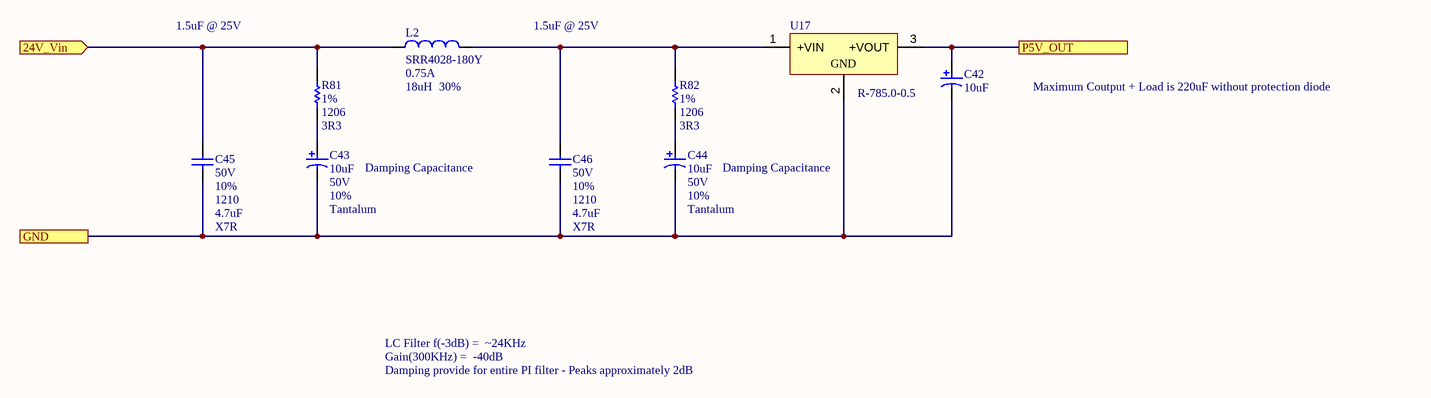
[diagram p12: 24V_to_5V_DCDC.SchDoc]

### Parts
C42  value 10uF  [KEMT-D-7343-31-2_L]  (hidden comment: T491D106K050AT)
C43  value 10uF  Voltage: 50V  Tolerance: 10%  Dielectric Material: Tantalum  [KEMT-D-7343-31-2_L]  (hidden comment: T491D106K050AT)
C44  value 10uF  Voltage: 50V  Tolerance: 10%  Dielectric Material: Tantalum  [KEMT-D-7343-31-2_L]  (hidden comment: T491D106K050AT)
C45  value 4.7uF  Voltage Rating: 50V  Tolerance: 10%  Case/Package: 1210  Dielectric: X7R  [CAPC3225X270X30ML30]  (hidden comment: Capacitor 4.7uF 10%, 50V, X7R, 1210)
C46  value 4.7uF  Voltage Rating: 50V  Tolerance: 10%  Case/Package: 1210  Dielectric: X7R  [CAPC3225X270X30ML30]  (hidden comment: Capacitor 4.7uF 10%, 50V, X7R, 1210)
L2  SRR4028-180Y  Inductance Tolerance: 30%  Saturation Current: 0.75A  Inductance: 18uH  [INDP4848X30M]
R81  value 3R3  Tolerance: 1%  Case/Package: 1206  [RESC3115X07M]  (hidden comment: Res Thick Film 1206 3.3 Ohm 1% 0.5W ±200ppm/°C Molded SMD Punched Carrier T/R)
R82  value 3R3  Tolerance: 1%  Case/Package: 1206  [RESC3115X07M]  (hidden comment: Res Thick Film 1206 3.3 Ohm 1% 0.5W ±200ppm/°C Molded SMD Punched Carrier T/R)
U17  R-785.0-0.5  [REPO-R-78XX-3_V]

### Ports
24V_Vin (in), GND, P5V_OUT

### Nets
COIL_DRV_HIGH: C45.2 L2.1 R81.2 ; port 24V_Vin
LV_GND: C42.2 C43.2 C44.2 C45.1 C46.1 U17.2(GND) ; port GND
LV_P5V: C42.1 U17.3(+VOUT) ; port P5V_OUT
NetC43_1: C43.1 R81.1
NetC44_1: C44.1 R82.1
NetC46_2: C46.2 L2.2 R82.2 U17.1(+VIN)

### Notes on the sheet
- 1.5uF @ 25V
- Maximum Coutput + Load is 220uF without protection diode
- Damping Capacitance
- LC Filter f(-3dB) =  |4KHz
- Gain(300KHz) =  -40dB
- Damping provide for entire PI filter - Peaks approximately 2dB

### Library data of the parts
C42 = CMP-001-00088-10: 10uF Solid MnO2 Tantalum Electrolytic Capacitor; 50 V dc +/-10%; T491 Series; Manufacturer: KEMET; Voltage: 50V; Tolerance: 10%; Life (Hours): 2000Hour; Dissipation Factor: 6%; Ripple Current: 433mA; Leakage Current: 5uA; ESR (Equivalent Series Resistance): 800mR; Polarity: Polar
C43 C44 = CMP-001-00088-10: as C52 on sheet 24V_to_12V_DCDC
C45 C46 = CMP-001-00183-10: as C13 on sheet Local_Power_Supplies
L2 = CMP-006-00041-3: as L1 on sheet Local_Power_Supplies
R81 R82 = CMP-009-01213-6: as R85 on sheet 24V_to_12V_DCDC
U17 = CMP-019-00062-2: 0.5A DC/DC-Converter 'INNOLINE' SIP3 reg; V. In: 6.5-32; V. Out: 5.0; mA. Out: 500; Nominal Input Voltage: 24V; Max Power Dissipation: 3W; Efficiency: 94%; Min Input Voltage (DC): 6.5V; Current - Output 1: 500mA; Isolation: Non-Isolated; Max Input Voltage: 32V; Switching Frequency: 380kHz; Max Output Power: 2.5W; Max Output Voltage: 5V; Isolation Voltage: 2kV

## Sheet Mechanical.SchDoc: MARS2 - IPB - Mechanicals
size 431 x 279 mm; Organization: ORGANIZATION; Address1: APPLIED PHYSICS LAB; Address2: UNIVERSITY OF WASHINGTON; Address3: 1013 NE 40TH STREET; Address4: SEATTLE, WA 98105; Revision: -; SheetNumber: 14; SheetTotal: 23; ENG_APP_DATE: --/--/--; DSN_APP_DATE: --/--/--; CHK_APP_DATE: --/--/--
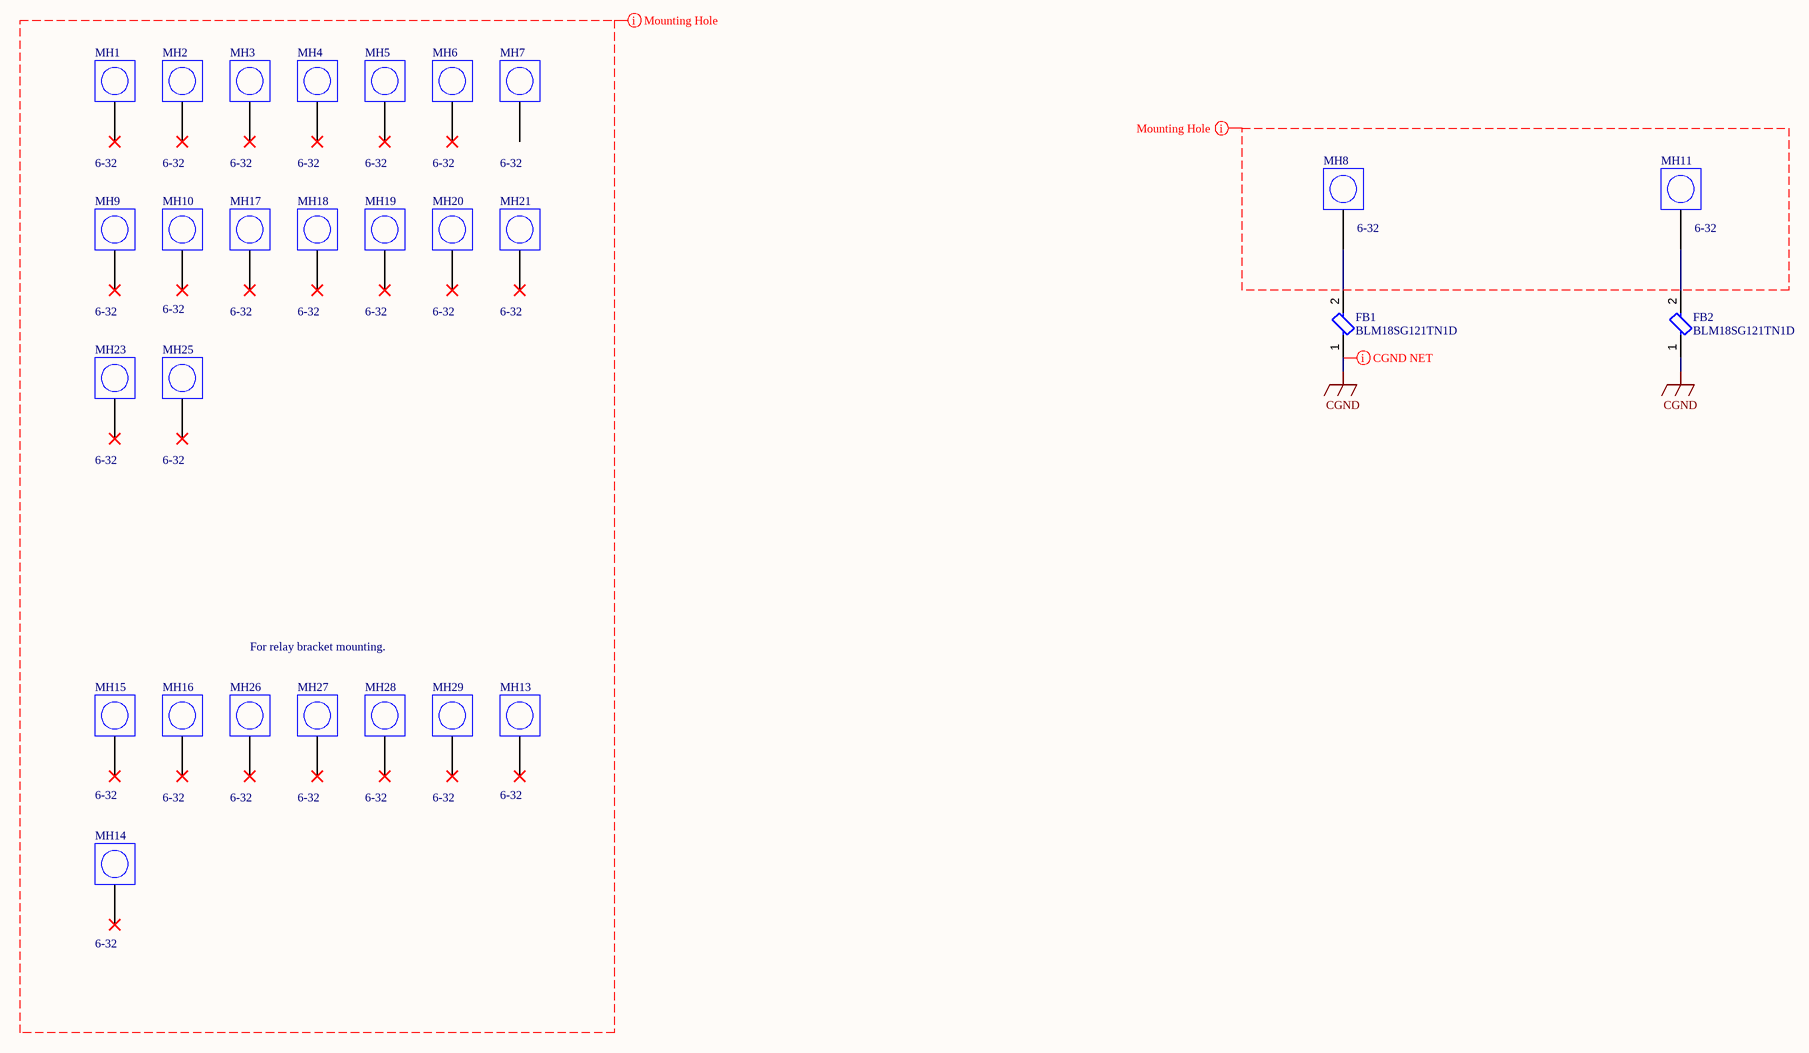
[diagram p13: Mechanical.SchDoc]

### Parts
FB1  BLM18SG121TN1D  [FP-BLM18-0_15-t0_5-d1_2-IPC_B]
FB2  BLM18SG121TN1D  [FP-BLM18-0_15-t0_5-d1_2-IPC_B]
MH1  Fastener Size: 6-32  [MH-M3-Footprint-1 - Oversized MARS2]  (hidden comment: MH-MARS2-6-32)  (no BOM)
MH2  Fastener Size: 6-32  [MH-M3-Footprint-1 - Oversized MARS2]  (hidden comment: MH-MARS2-6-32)  (no BOM)
MH3  Fastener Size: 6-32  [MH-M3-Footprint-1 - Oversized MARS2]  (hidden comment: MH-MARS2-6-32)  (no BOM)
MH4  Fastener Size: 6-32  [MH-M3-Footprint-1 - Oversized MARS2]  (hidden comment: MH-MARS2-6-32)  (no BOM)
MH5  Fastener Size: 6-32  [MH-M3-Footprint-1 - Oversized MARS2]  (hidden comment: MH-MARS2-6-32)  (no BOM)
MH6  Fastener Size: 6-32  [MH-M3-Footprint-1 - Oversized MARS2]  (hidden comment: MH-MARS2-6-32)  (no BOM)
MH7  Fastener Size: 6-32  [MH-M3-Footprint-1 - Oversized MARS2]  (hidden comment: MH-MARS2-6-32)  (no BOM)
MH8  Fastener Size: 6-32  [MH-M3-Footprint-1 - Oversized MARS2]  (hidden comment: MH-MARS2-6-32)  (no BOM)
MH9  Fastener Size: 6-32  [MH-M3-Footprint-1 - Oversized MARS2]  (hidden comment: MH-MARS2-6-32)  (no BOM)
MH10  Fastener Size: 6-32  [MH-M3-Footprint-1 - Oversized MARS2]  (hidden comment: MH-MARS2-6-32)  (no BOM)
MH11  Fastener Size: 6-32  [MH-M3-Footprint-1 - Oversized MARS2]  (hidden comment: MH-MARS2-6-32)  (no BOM)
MH13  Fastener Size: 6-32  [MH-M3-Footprint-1 - Oversized MARS2]  (hidden comment: MH-MARS2-6-32)  (no BOM)
MH14  Fastener Size: 6-32  [MH-M3-Footprint-1 - Oversized MARS2]  (hidden comment: MH-MARS2-6-32)  (no BOM)
MH15  Fastener Size: 6-32  [MH-M3-Footprint-1 - Oversized MARS2]  (hidden comment: MH-MARS2-6-32)  (no BOM)
MH16  Fastener Size: 6-32  [MH-M3-Footprint-1 - Oversized MARS2]  (hidden comment: MH-MARS2-6-32)  (no BOM)
MH17  Fastener Size: 6-32  [MH-M3-Footprint-1 - Oversized MARS2]  (hidden comment: MH-MARS2-6-32)  (no BOM)
MH18  Fastener Size: 6-32  [MH-M3-Footprint-1 - Oversized MARS2]  (hidden comment: MH-MARS2-6-32)  (no BOM)
MH19  Fastener Size: 6-32  [MH-M3-Footprint-1 - Oversized MARS2]  (hidden comment: MH-MARS2-6-32)  (no BOM)
MH20  Fastener Size: 6-32  [MH-M3-Footprint-1 - Oversized MARS2]  (hidden comment: MH-MARS2-6-32)  (no BOM)
MH21  Fastener Size: 6-32  [MH-M3-Footprint-1 - Oversized MARS2]  (hidden comment: MH-MARS2-6-32)  (no BOM)
MH23  Fastener Size: 6-32  [MH-M3-Footprint-1 - Oversized MARS2]  (hidden comment: MH-MARS2-6-32)  (no BOM)
MH25  Fastener Size: 6-32  [MH-M3-Footprint-1 - Oversized MARS2]  (hidden comment: MH-MARS2-6-32)  (no BOM)
MH26  Fastener Size: 6-32  [MH-M3-Footprint-1 - Oversized MARS2]  (hidden comment: MH-MARS2-6-32)  (no BOM)
MH27  Fastener Size: 6-32  [MH-M3-Footprint-1 - Oversized MARS2]  (hidden comment: MH-MARS2-6-32)  (no BOM)
MH28  Fastener Size: 6-32  [MH-M3-Footprint-1 - Oversized MARS2]  (hidden comment: MH-MARS2-6-32)  (no BOM)
MH29  Fastener Size: 6-32  [MH-M3-Footprint-1 - Oversized MARS2]  (hidden comment: MH-MARS2-6-32)  (no BOM)

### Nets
CGND: FB1.1 FB2.1
NetFB1_2: FB1.2 MH8.1
NetFB2_2: FB2.2 MH11.1

Not connected (* = marked no-connect by the designer): MH1 1*; MH2 1*; MH3 1*; MH4 1*; MH5 1*; MH6 1*; MH7 1; MH9 1*; MH10 1*; MH13 1*; MH14 1*; MH15 1*; MH16 1*; MH17 1*; MH18 1*; MH19 1*; MH20 1*; MH21 1*; MH23 1*; MH25 1*; MH26 1*; MH27 1*; MH28 1*; MH29 1*

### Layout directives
net class CGND: CGND
CompClassName: Mounting Hole: (no net found under the mark)

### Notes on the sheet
- For relay bracket mounting.

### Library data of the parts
FB1 FB2 = CMP-00000-2: Ferrite Beads Multi-Layer 120Ohm 25% 100MHz 3A 0.025Ohm DCR 0603 T/R; DC Resistance (DCR): 25mR; Number of Circuits: 1; Shielding: Unshielded; Material: Steel,Ferrite; Impedance: 120R
MH1-MH11 MH13-MH21 MH23 MH25-MH29 = CMP-00028-00015-2: MARS2 Project 6-32 Mounting Hole Plated .; Plated: Yes

## Sheet Interface_Channels_Main.SchDoc
size 431 x 279 mm; Organization: ORGANIZATION; Address1: APPLIED PHYSICS LAB; Address2: UNIVERSITY OF WASHINGTON; Address3: 1013 NE 40TH STREET; Address4: SEATTLE, WA 98105; SheetTitle: Interface Channel - High Level; Revision: -; ENG_APP_DATE: --/--/--; DSN_APP_DATE: --/--/--; CHK_APP_DATE: --/--/--
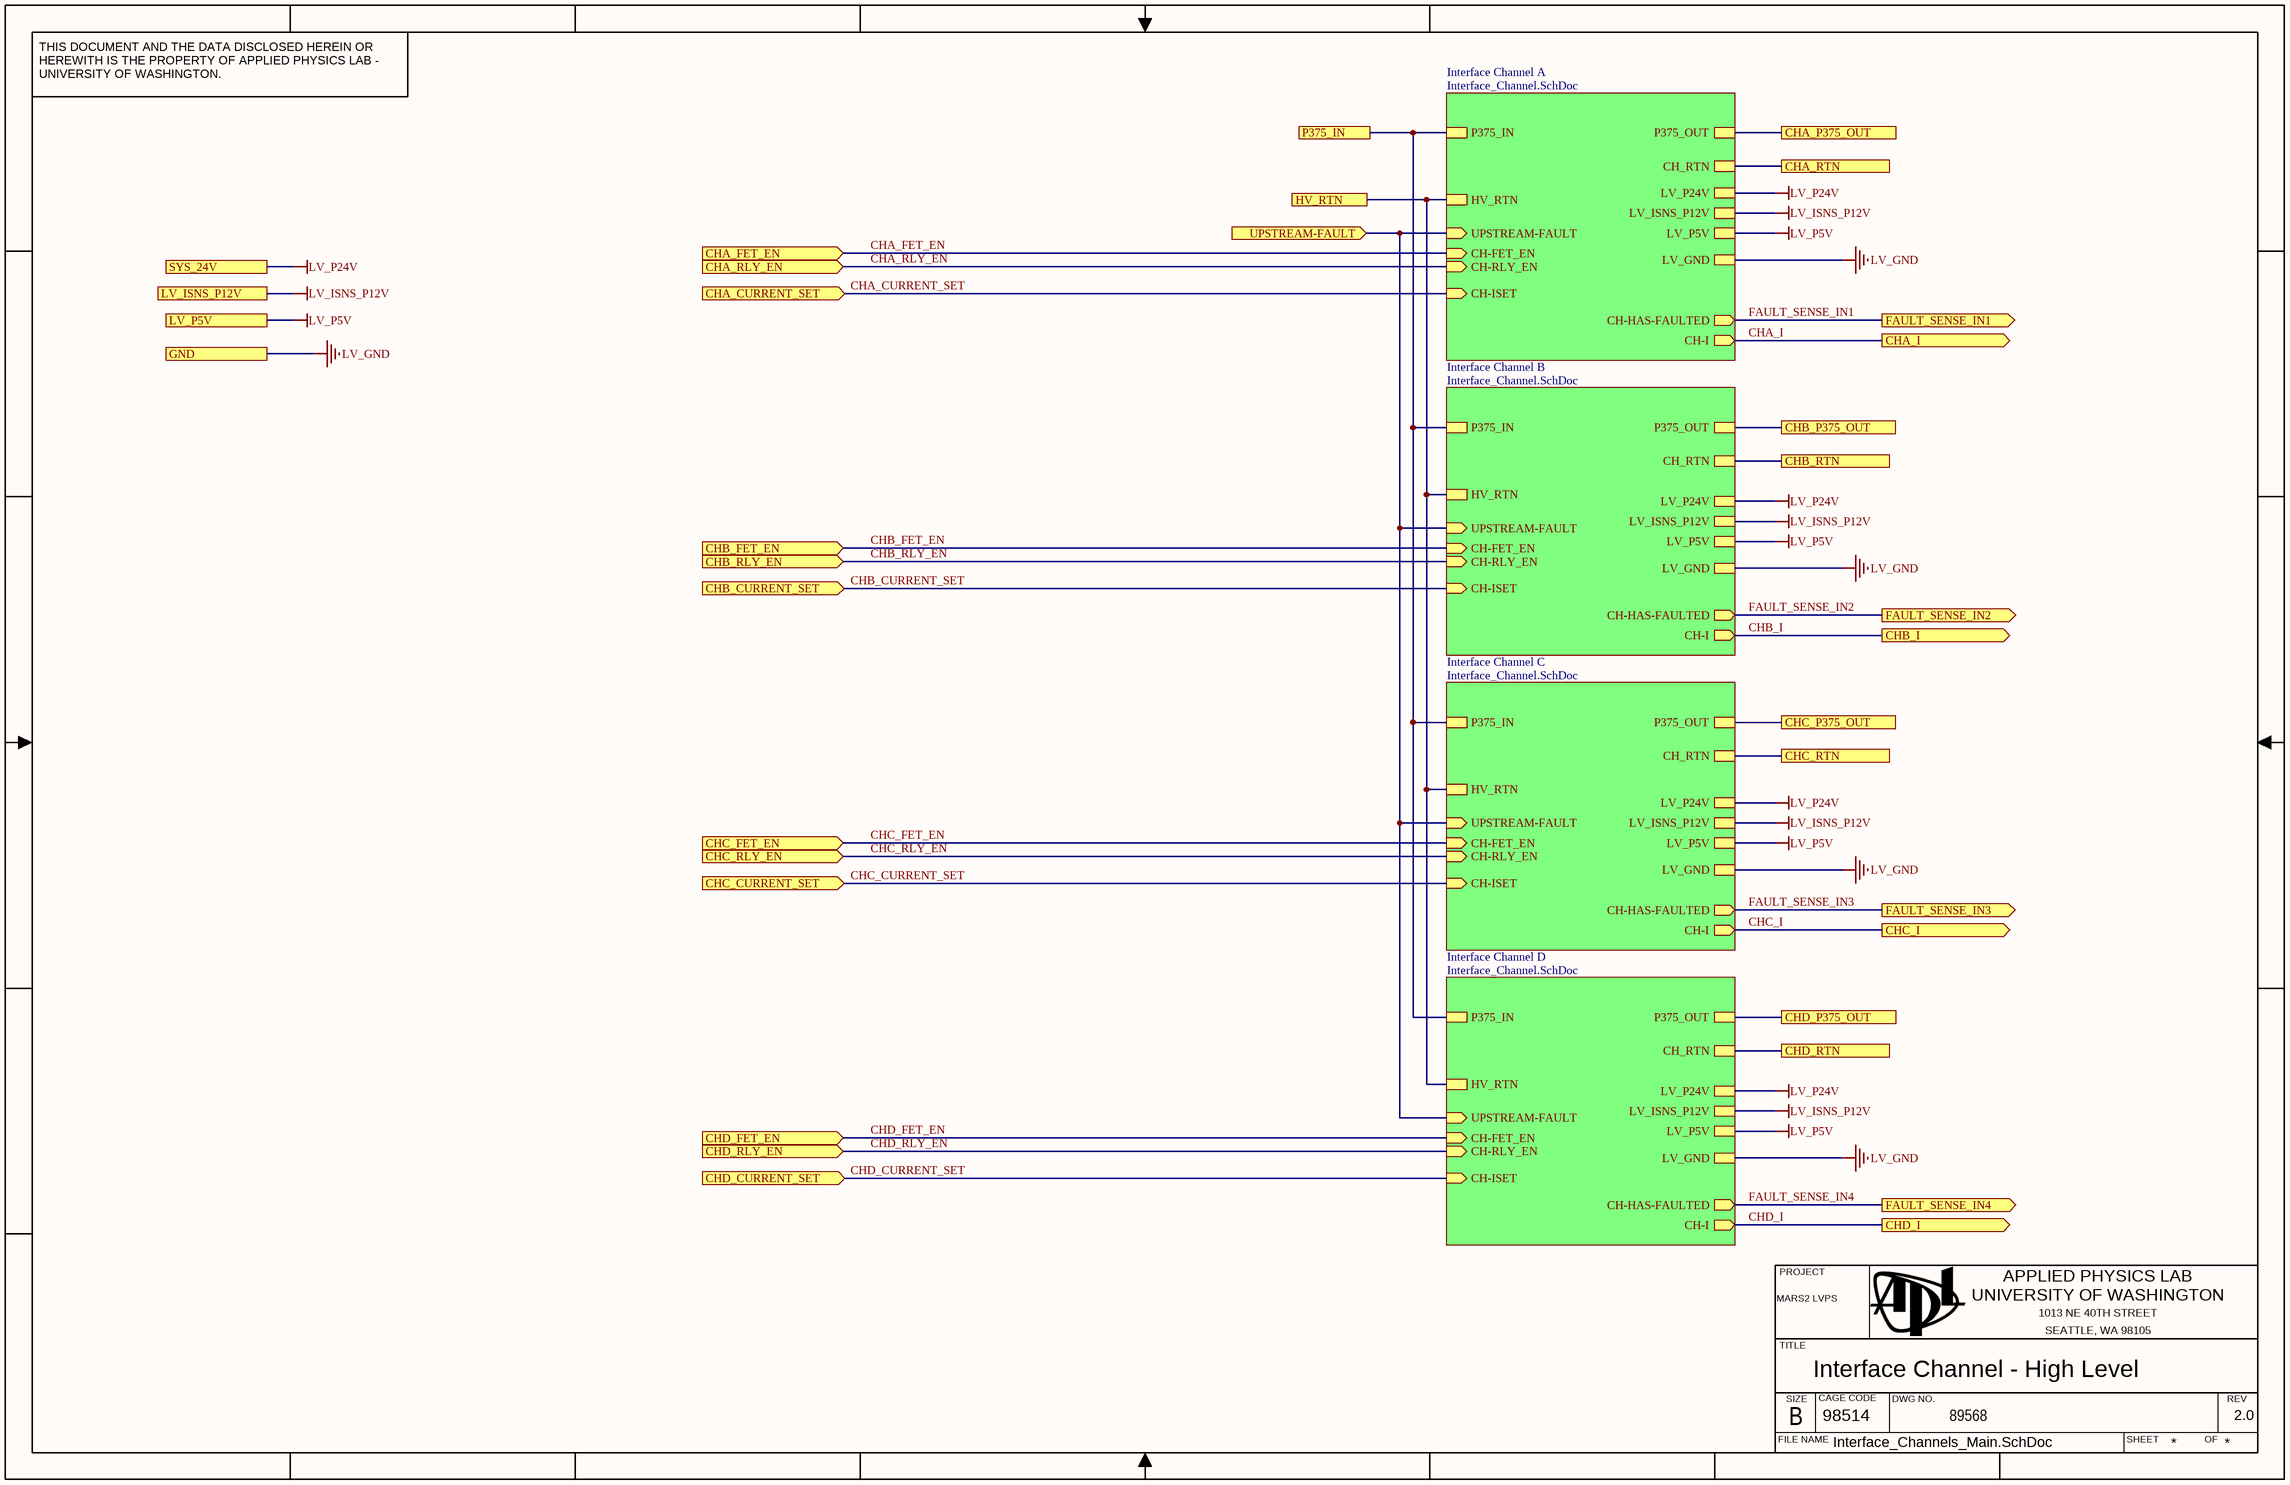
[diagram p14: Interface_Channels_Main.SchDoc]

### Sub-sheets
Interface Channel A = Interface_Channel.SchDoc: P375_IN, HV_RTN, P375_OUT, CH-HAS-FAULTED (out), CH-I (out), CH-RLY_EN (in), CH-FET_EN (in), CH-ISET (in), UPSTREAM-FAULT (in), CH_RTN, LV_GND, LV_P5V, LV_P24V, LV_ISNS_P12V
Interface Channel B = Interface_Channel.SchDoc: P375_IN, HV_RTN, P375_OUT, CH-HAS-FAULTED (out), CH-I (out), CH-RLY_EN (in), CH-FET_EN (in), CH-ISET (in), UPSTREAM-FAULT (in), CH_RTN, LV_GND, LV_P5V, LV_P24V, LV_ISNS_P12V
Interface Channel C = Interface_Channel.SchDoc: P375_IN, HV_RTN, P375_OUT, CH-HAS-FAULTED (out), CH-I (out), CH-RLY_EN (in), CH-FET_EN (in), CH-ISET (in), UPSTREAM-FAULT (in), CH_RTN, LV_GND, LV_P5V, LV_P24V, LV_ISNS_P12V
Interface Channel D = Interface_Channel.SchDoc: P375_IN, HV_RTN, P375_OUT, CH-HAS-FAULTED (out), CH-I (out), CH-RLY_EN (in), CH-FET_EN (in), CH-ISET (in), UPSTREAM-FAULT (in), CH_RTN, LV_GND, LV_P5V, LV_P24V, LV_ISNS_P12V

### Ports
CHA_CURRENT_SET (in), CHA_FET_EN (in), CHA_I (out), CHA_P375_OUT, CHA_RLY_EN (in), CHA_RTN, CHB_CURRENT_SET (in), CHB_FET_EN (in), CHB_I (out), CHB_P375_OUT, CHB_RLY_EN (in), CHB_RTN, CHC_CURRENT_SET (in), CHC_FET_EN (in), CHC_I (out), CHC_P375_OUT, CHC_RLY_EN (in), CHC_RTN, CHD_CURRENT_SET (in), CHD_FET_EN (in), CHD_I (out), CHD_P375_OUT, CHD_RLY_EN (in), CHD_RTN, FAULT_SENSE_IN1 (out), FAULT_SENSE_IN2 (out), FAULT_SENSE_IN3 (out), FAULT_SENSE_IN4 (out), GND, HV_RTN, LV_ISNS_P12V, LV_P5V, P375_IN, SYS_24V, UPSTREAM-FAULT (in)

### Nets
LV_GND: port GND, sheet Interface Channel A/LV_GND, sheet Interface Channel B/LV_GND, sheet Interface Channel C/LV_GND, sheet Interface Channel D/LV_GND
LV_ISNS_P12V: port LV_ISNS_P12V, sheet Interface Channel A/LV_ISNS_P12V, sheet Interface Channel B/LV_ISNS_P12V, sheet Interface Channel C/LV_ISNS_P12V, sheet Interface Channel D/LV_ISNS_P12V
LV_P5V: port LV_P5V, sheet Interface Channel A/LV_P5V, sheet Interface Channel B/LV_P5V, sheet Interface Channel C/LV_P5V, sheet Interface Channel D/LV_P5V
LV_P24V: port SYS_24V, sheet Interface Channel A/LV_P24V, sheet Interface Channel B/LV_P24V, sheet Interface Channel C/LV_P24V, sheet Interface Channel D/LV_P24V  [project net COIL_DRV_HIGH]
N187: port HV_RTN, sheet Interface Channel A/HV_RTN, sheet Interface Channel B/HV_RTN, sheet Interface Channel C/HV_RTN, sheet Interface Channel D/HV_RTN
CHA_CURRENT_SET: port CHA_CURRENT_SET, sheet Interface Channel A/CH-ISET
CHA_FET_EN: port CHA_FET_EN, sheet Interface Channel A/CH-FET_EN
CHA_I: port CHA_I, sheet Interface Channel A/CH-I
CHA_RLY_EN: port CHA_RLY_EN, sheet Interface Channel A/CH-RLY_EN
CHB_CURRENT_SET: port CHB_CURRENT_SET, sheet Interface Channel B/CH-ISET
CHB_FET_EN: port CHB_FET_EN, sheet Interface Channel B/CH-FET_EN
CHB_I: port CHB_I, sheet Interface Channel B/CH-I
CHB_RLY_EN: port CHB_RLY_EN, sheet Interface Channel B/CH-RLY_EN
CHC_CURRENT_SET: port CHC_CURRENT_SET, sheet Interface Channel C/CH-ISET
CHC_FET_EN: port CHC_FET_EN, sheet Interface Channel C/CH-FET_EN
CHC_I: port CHC_I, sheet Interface Channel C/CH-I
CHC_RLY_EN: port CHC_RLY_EN, sheet Interface Channel C/CH-RLY_EN
CHD_CURRENT_SET: port CHD_CURRENT_SET, sheet Interface Channel D/CH-ISET
CHD_FET_EN: port CHD_FET_EN, sheet Interface Channel D/CH-FET_EN
CHD_I: port CHD_I, sheet Interface Channel D/CH-I
CHD_RLY_EN: port CHD_RLY_EN, sheet Interface Channel D/CH-RLY_EN
FAULT_SENSE_IN0: port UPSTREAM-FAULT, sheet Interface Channel A/UPSTREAM-FAULT, sheet Interface Channel B/UPSTREAM-FAULT, sheet Interface Channel C/UPSTREAM-FAULT, sheet Interface Channel D/UPSTREAM-FAULT
FAULT_SENSE_IN1: port FAULT_SENSE_IN1, sheet Interface Channel A/CH-HAS-FAULTED
FAULT_SENSE_IN2: port FAULT_SENSE_IN2, sheet Interface Channel B/CH-HAS-FAULTED
FAULT_SENSE_IN3: port FAULT_SENSE_IN3, sheet Interface Channel C/CH-HAS-FAULTED
FAULT_SENSE_IN4: port FAULT_SENSE_IN4, sheet Interface Channel D/CH-HAS-FAULTED
NetD1_A_1: port CHA_RTN, sheet Interface Channel A/CH_RTN
NetD1_A_4: port CHA_P375_OUT, sheet Interface Channel A/P375_OUT
NetD1_B_1: port CHB_RTN, sheet Interface Channel B/CH_RTN
NetD1_B_4: port CHB_P375_OUT, sheet Interface Channel B/P375_OUT
NetD1_C_1: port CHC_RTN, sheet Interface Channel C/CH_RTN
NetD1_C_4: port CHC_P375_OUT, sheet Interface Channel C/P375_OUT
NetD1_D_1: port CHD_RTN, sheet Interface Channel D/CH_RTN
NetD1_D_4: port CHD_P375_OUT, sheet Interface Channel D/P375_OUT
NetU4_A_3: port P375_IN, sheet Interface Channel A/P375_IN, sheet Interface Channel B/P375_IN, sheet Interface Channel C/P375_IN, sheet Interface Channel D/P375_IN

## Sheet Interface_Channel.SchDoc: MARS2 - IPB - Instrument Channel
size 431 x 279 mm; Organization: ORGANIZATION; Address1: APPLIED PHYSICS LAB; Address2: UNIVERSITY OF WASHINGTON; Address3: 1013 NE 40TH STREET; Address4: SEATTLE, WA 98105; Revision: -; SheetNumber: 16; SheetTotal: 23; ENG_APP_DATE: --/--/--; DSN_APP_DATE: --/--/--; CHK_APP_DATE: --/--/--
Used 4 times, as channels Designator/Interface Channel A, Designator/Interface Channel B, Designator/Interface Channel C, Designator/Interface Channel D. Parts and nets are listed once, with the designators drawn on the sheet.
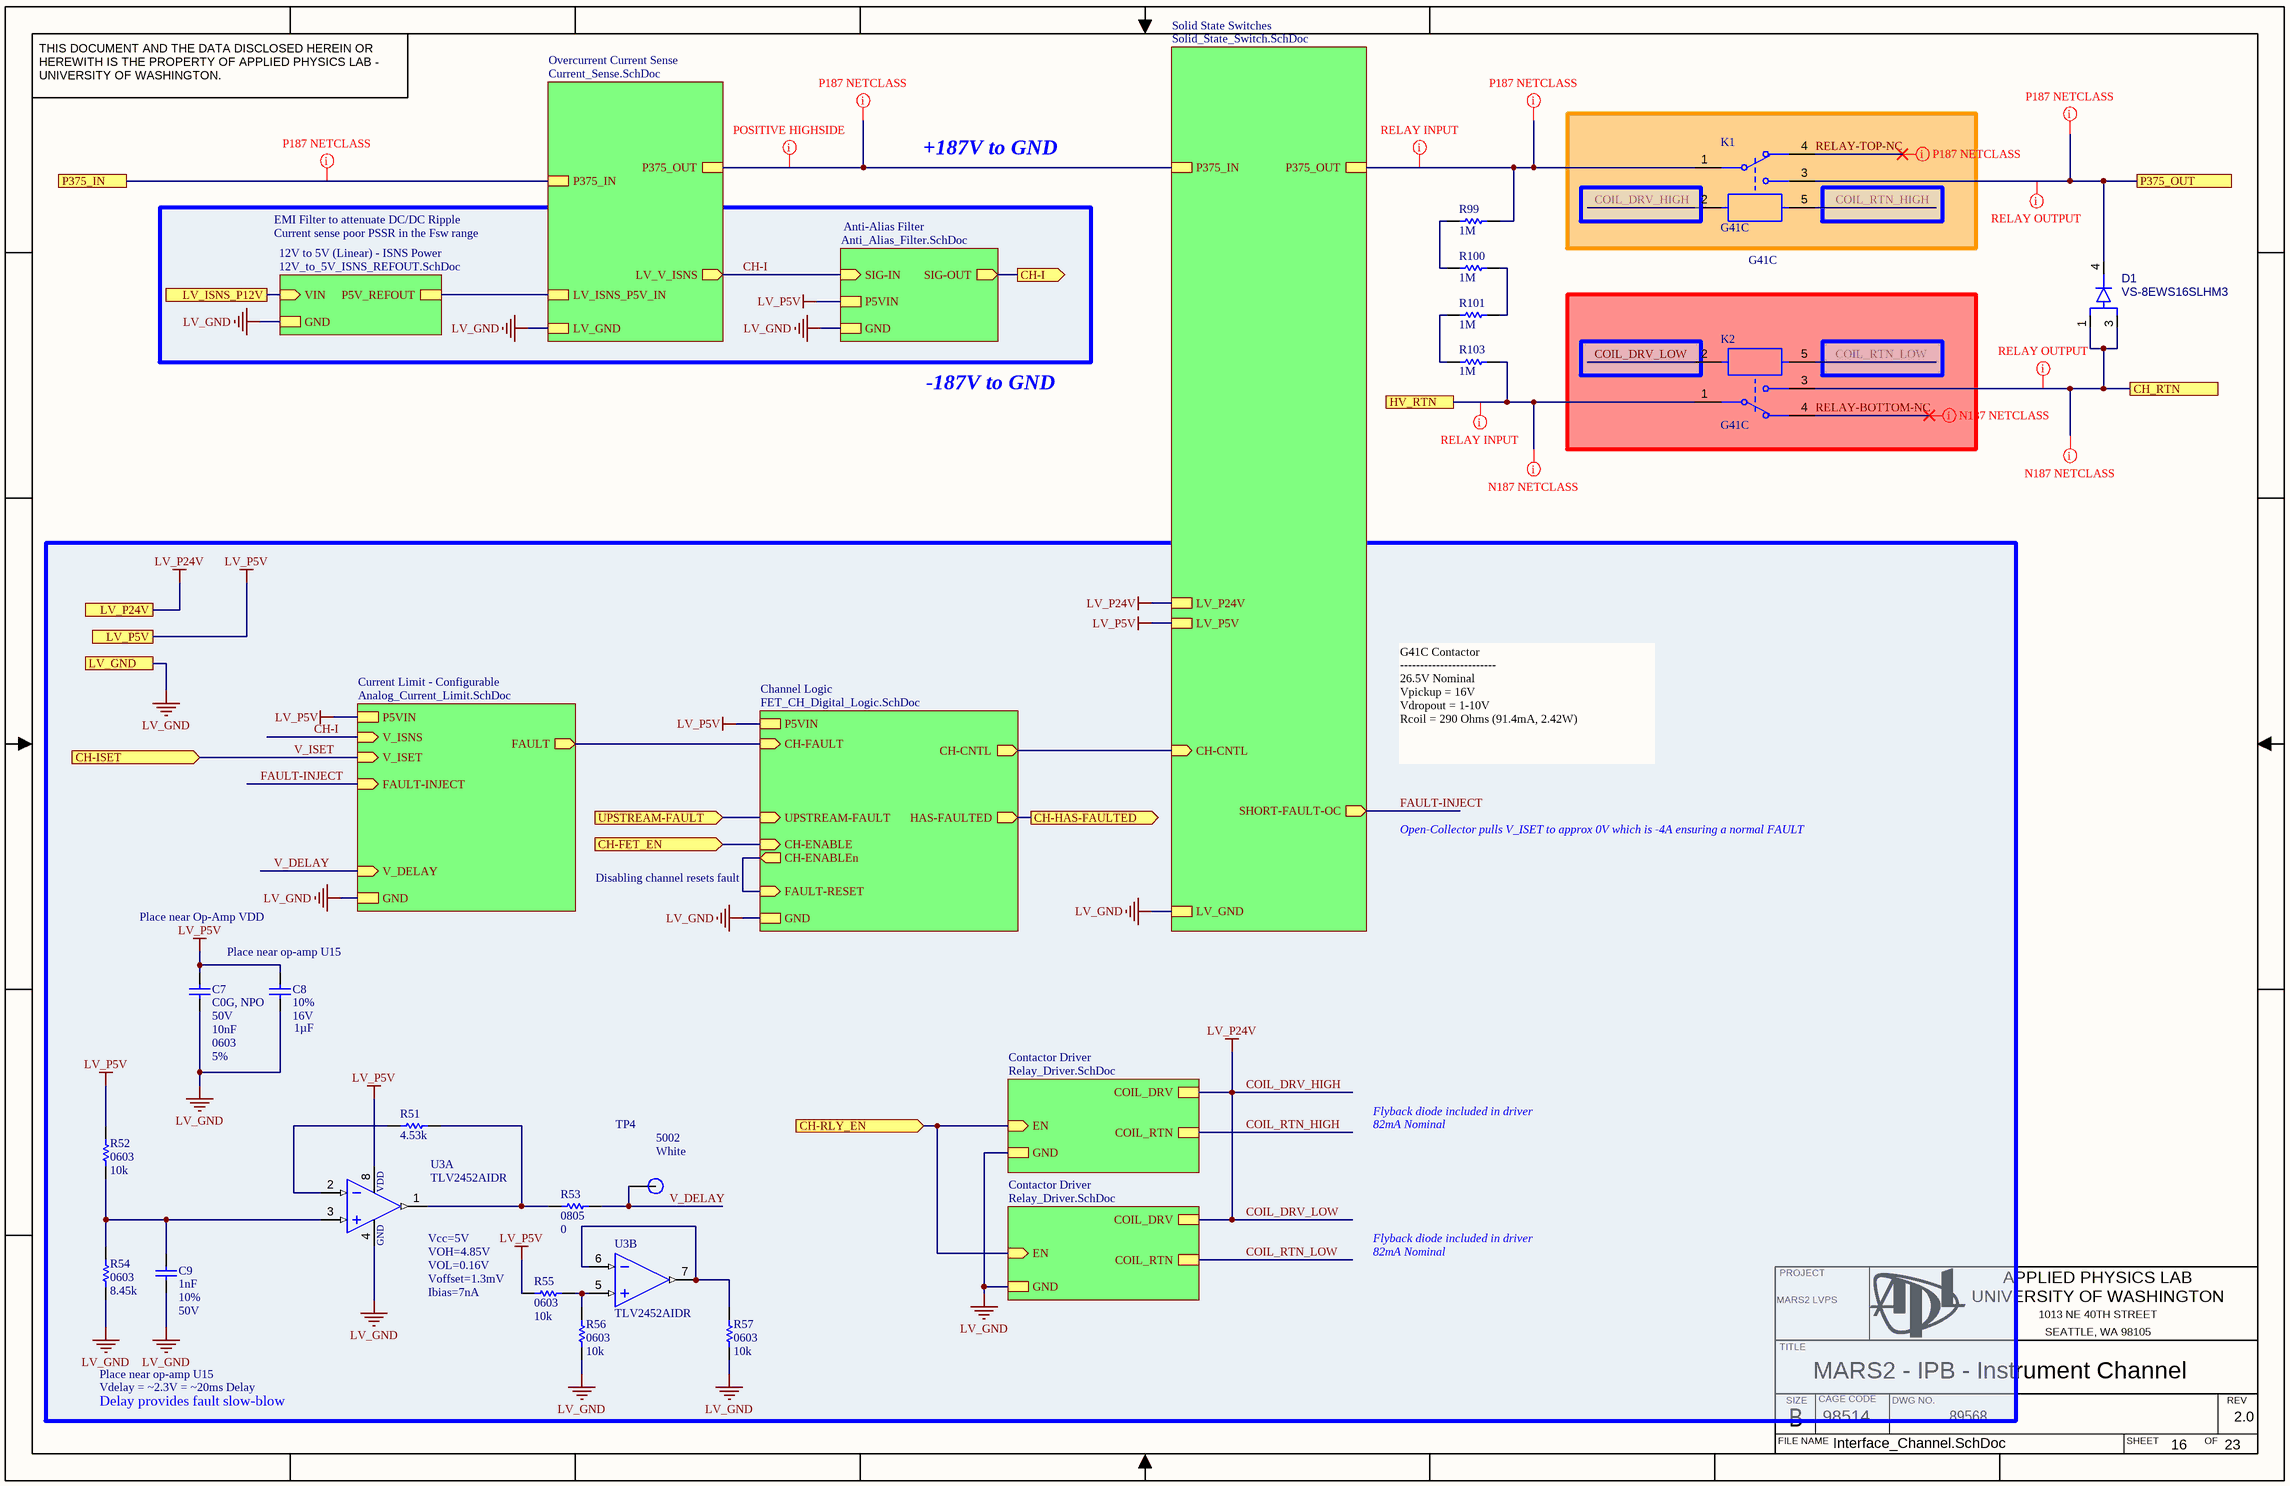
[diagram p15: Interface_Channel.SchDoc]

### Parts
C7  Dielectric: C0G, NPO  Voltage Rating: 50V  Capacitance: 10nF  Case/Package: 0603  Tolerance: 5%  [CAPC1608X90X40ML10T20]  (hidden comment: Capacitor 10nF +/- 5%, 50V, C0G, 0603)
C8  value 1µF  Tolerance: 10%  Voltage Rating: 16V  [CAPC1608X94X35NL15T15]  (hidden comment: Capacitor 1 uF +/- 10% 16 V 0603)
C9  value 1nF  Tolerance: 10%  Voltage Rating: 50V  [CAPC0402(1005)33_L]  (hidden comment: Capacitor 1nF +/-20% 50V 0402)
D1  VS-8EWS16SLHM3  [TO-252AA-IPC_A-APL]
K1  G41C  [G41C]
K2  G41C  [G41C]
R51  value 4.53k  [RESC1609X50X30ML08T20]  (hidden comment: Resistor 4K53 +/-1% 0603 100 mW)
R52  value 10k  Case/Package: 0603  [RESC1608X55X25ML10T15]  (hidden comment: Resistor 10k +/-1% 0603 100 mW)
R53  value 0  Case/Package: 0805  [RESC2013X60X35ML10T20]  (hidden comment: Resistor 0R +/- 5% 0805 125 mW)
R54  value 8.45k  Case/Package: 0603  [RESC1609X50X30ML08T20]  (hidden comment: Resistor 8K45 +/-1% 0603 100 mW)
R55  value 10k  Case/Package: 0603  [RESC1608X55X25ML10T15]  (hidden comment: Resistor 10k +/-1% 0603 100 mW)
R56  value 10k  Case/Package: 0603  [RESC1608X55X25ML10T15]  (hidden comment: Resistor 10k +/-1% 0603 100 mW)
R57  value 10k  Case/Package: 0603  [RESC1608X55X25ML10T15]  (hidden comment: Resistor 10k +/-1% 0603 100 mW)
R99  value 1M  [PANASONIC_ERJ6E]  (hidden comment: RES 0805 1M00 1%)
R100  value 1M  [PANASONIC_ERJ6E]  (hidden comment: RES 0805 1M00 1%)
R101  value 1M  [PANASONIC_ERJ6E]  (hidden comment: RES 0805 1M00 1%)
R103  value 1M  [PANASONIC_ERJ6E]  (hidden comment: RES 0805 1M00 1%)
TP4  5002  Color: White  [Keystone 5002]
U3  TLV2452AIDR  [D0008A_L]  (parts A,B of 2)

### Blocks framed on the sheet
Delay provides fault slow-blow: C7-C9 R51-R57 TP4 U3

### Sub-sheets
12V to 5V (Linear) - ISNS Power = 12V_to_5V_ISNS_REFOUT.SchDoc: VIN (in), P5V_REFOUT, GND
Anti-Alias Filter = Anti_Alias_Filter.SchDoc: SIG-IN (in), SIG-OUT (out), P5VIN, GND
Channel Logic = FET_CH_Digital_Logic.SchDoc: CH-FAULT (in), CH-CNTL (out), UPSTREAM-FAULT (in), CH-ENABLE (in), HAS-FAULTED (out), FAULT-RESET (in), CH-ENABLEn (out), GND, P5VIN
Contactor Driver = Relay_Driver.SchDoc: COIL_DRV, COIL_RTN, EN (in), GND
Contactor Driver = Relay_Driver.SchDoc: COIL_DRV, COIL_RTN, EN (in), GND
Current Limit - Configurable = Analog_Current_Limit.SchDoc: V_ISNS (in), FAULT (out), V_ISET (in), V_DELAY (in), GND, P5VIN, FAULT-INJECT (in)
Overcurrent Current Sense = Current_Sense.SchDoc: P375_IN, P375_OUT, LV_V_ISNS (out), LV_ISNS_P5V_IN, LV_GND
Solid State Switches = Solid_State_Switch.SchDoc: P375_IN, P375_OUT, CH-CNTL (in), LV_P5V, LV_GND, LV_P24V, SHORT-FAULT-OC (out)

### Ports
CH-FET_EN (in), CH-HAS-FAULTED (out), CH-I (out), CH-ISET (in), CH-RLY_EN (in), CH_RTN, HV_RTN, LV_GND, LV_ISNS_P12V, LV_P5V, LV_P24V, P375_IN, P375_OUT, UPSTREAM-FAULT (in)

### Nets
COIL_DRV_HIGH: K1.2 K2.2 ; port LV_P24V, sheet Contactor Driver/COIL_DRV, sheet Contactor Driver/COIL_DRV, sheet Solid State Switches/LV_P24V  [also labelled COIL_DRV_LOW, LV_P24V]
LV_GND: C7.2 C8.1 C9.1 R54.1 R56.1 R57.1 U3.4(GND) ; port LV_GND, sheet Overcurrent Current Sense/LV_GND, sheet Channel Logic/GND, sheet Current Limit - Configurable/GND, sheet Contactor Driver/GND, sheet Contactor Driver/GND, sheet Anti-Alias Filter/GND, sheet 12V to 5V (Linear) - ISNS Power/GND, sheet Solid State Switches/LV_GND
LV_P5V: C7.1 C8.2 R52.2 R55.1 U3.8(VDD+) ; port LV_P5V, sheet Channel Logic/P5VIN, sheet Current Limit - Configurable/P5VIN, sheet Anti-Alias Filter/P5VIN, sheet Solid State Switches/LV_P5V
CH-FET_EN: port CH-FET_EN, sheet Channel Logic/CH-ENABLE
CH-HAS-FAULTED: port CH-HAS-FAULTED, sheet Channel Logic/HAS-FAULTED
CH-I: sheet Overcurrent Current Sense/LV_V_ISNS, sheet Current Limit - Configurable/V_ISNS, sheet Anti-Alias Filter/SIG-IN
CH-I: port CH-I, sheet Anti-Alias Filter/SIG-OUT  [a separate net that carries the same name]
CH-RLY_EN: port CH-RLY_EN, sheet Contactor Driver/EN, sheet Contactor Driver/EN
CH_RTN: D1.1(A) D1.3(A) K2.3 ; port CH_RTN
COIL_RTN_HIGH: K1.5 ; sheet Contactor Driver/COIL_RTN
COIL_RTN_LOW: K2.5 ; sheet Contactor Driver/COIL_RTN
FAULT-INJECT: sheet Current Limit - Configurable/FAULT-INJECT, sheet Solid State Switches/SHORT-FAULT-OC
HV_RTN: K2.1 R103.1 ; port HV_RTN
LV_ISNS_P12V: port LV_ISNS_P12V, sheet 12V to 5V (Linear) - ISNS Power/VIN
P375_IN: port P375_IN, sheet Overcurrent Current Sense/P375_IN
P375_OUT: D1.4(K) K1.3 ; port P375_OUT
RELAY-BOTTOM-NC: K2.4  [project net RELAY-BOTTOM-NC_16]
RELAY-TOP-NC: K1.4  [project net RELAY-TOP-NC_16]
UPSTREAM-FAULT: port UPSTREAM-FAULT, sheet Channel Logic/UPSTREAM-FAULT
V_DELAY: R53.1 TP4.1 ; sheet Current Limit - Configurable/V_DELAY
V_ISET: port CH-ISET, sheet Current Limit - Configurable/V_ISET
NetC9_2: C9.2 R52.1 R54.2 U3.3(IN1+)
NetK1_1: K1.1 R99.1 ; sheet Solid State Switches/P375_OUT
NetR51_1: R51.1 U3.2(IN1-)
NetR51_2: R51.2 R53.2 U3.1(OUT1)
NetR55_2: R55.2 R56.2 U3.5(IN2+)
NetR57_2: R57.2 U3.6(IN2-) U3.7(OUT2)
NetR99_2: R99.2 R100.2
NetR100_1: R100.1 R101.1
NetR101_2: R101.2 R103.2
(unnamed): sheet Overcurrent Current Sense/P375_OUT, sheet Solid State Switches/P375_IN
(unnamed): sheet Overcurrent Current Sense/LV_ISNS_P5V_IN, sheet 12V to 5V (Linear) - ISNS Power/P5V_REFOUT  [a separate net that carries the same name]
(unnamed): sheet Channel Logic/CH-FAULT, sheet Current Limit - Configurable/FAULT  [a separate net that carries the same name]
(unnamed): sheet Channel Logic/CH-CNTL, sheet Solid State Switches/CH-CNTL  [a separate net that carries the same name]
(unnamed): sheet Channel Logic/FAULT-RESET, sheet Channel Logic/CH-ENABLEn  [a separate net that carries the same name]

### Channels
Designator/Interface Channel A: designators end in _A; ports CH-FET_EN=CHA_FET_EN CH-HAS-FAULTED=FAULT_SENSE_IN1 CH-I=CHA_I CH-ISET=CHA_CURRENT_SET CH-RLY_EN=CHA_RLY_EN CH_RTN=NetD1_A_1 HV_RTN=N187 LV_GND=LV_GND LV_ISNS_P12V=LV_ISNS_P12V LV_P5V=LV_P5V LV_P24V=COIL_DRV_HIGH P375_IN=NetU4_A_3 P375_OUT=NetD1_A_4 UPSTREAM-FAULT=FAULT_SENSE_IN0
Designator/Interface Channel B: designators end in _B; ports CH-FET_EN=CHB_FET_EN CH-HAS-FAULTED=FAULT_SENSE_IN2 CH-I=CHB_I CH-ISET=CHB_CURRENT_SET CH-RLY_EN=CHB_RLY_EN CH_RTN=NetD1_B_1 HV_RTN=N187 LV_GND=LV_GND LV_ISNS_P12V=LV_ISNS_P12V LV_P5V=LV_P5V LV_P24V=COIL_DRV_HIGH P375_IN=NetU4_A_3 P375_OUT=NetD1_B_4 UPSTREAM-FAULT=FAULT_SENSE_IN0
Designator/Interface Channel C: designators end in _C; ports CH-FET_EN=CHC_FET_EN CH-HAS-FAULTED=FAULT_SENSE_IN3 CH-I=CHC_I CH-ISET=CHC_CURRENT_SET CH-RLY_EN=CHC_RLY_EN CH_RTN=NetD1_C_1 HV_RTN=N187 LV_GND=LV_GND LV_ISNS_P12V=LV_ISNS_P12V LV_P5V=LV_P5V LV_P24V=COIL_DRV_HIGH P375_IN=NetU4_A_3 P375_OUT=NetD1_C_4 UPSTREAM-FAULT=FAULT_SENSE_IN0
Designator/Interface Channel D: designators end in _D; ports CH-FET_EN=CHD_FET_EN CH-HAS-FAULTED=FAULT_SENSE_IN4 CH-I=CHD_I CH-ISET=CHD_CURRENT_SET CH-RLY_EN=CHD_RLY_EN CH_RTN=NetD1_D_1 HV_RTN=N187 LV_GND=LV_GND LV_ISNS_P12V=LV_ISNS_P12V LV_P5V=LV_P5V LV_P24V=COIL_DRV_HIGH P375_IN=NetU4_A_3 P375_OUT=NetD1_D_4 UPSTREAM-FAULT=FAULT_SENSE_IN0

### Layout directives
net class P187_REF: NetC59_A_1, NetD1_A_4, NetD8_A_2, NetU4_A_3, RELAY-TOP-NC_Interface Channel A
net class N187_REF: N187, NetD1_A_1, RELAY-BOTTOM-NC_Interface Channel A
net class RELAY INPUT: N187, NetD8_A_2
net class RELAY OUTPUT: NetD1_A_1, NetD1_A_4
net class POSITIVE HIGHSIDE: NetC59_A_1

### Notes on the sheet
- +187V to GND
- EMI Filter to attenuate DC/DC Ripple
- Current sense poor PSSR in the Fsw range
- (near K1) G41C
- -187V to GND
- G41C Contactor
  ------------------------
  26.5V Nominal
  Vpickup = 16V
  Vdropout = 1-10V
  Rcoil = 290 Ohms (91.4mA, 2.42W)
- Open-Collector pulls V_ISET to approx 0V which is -4A ensuring a normal FAULT
- Disabling channel resets fault
- Place near Op-Amp VDD
- Place near op-amp U15
- Flyback diode included in driver
- 82mA Nominal
- (near U3) Vcc=5V
- VOL=0.16V
- (near R55) Voffset=1.3mV
- Ibias=7nA
- (near U3) VOH=4.85V
- Vdelay = |.3V = |0ms Delay

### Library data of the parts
C7 = CMP-001-00166-10: Chip Capacitor, 10nF, +/- 5%, 50 V, C0G 0603 (1608 Metric); Capacitor Type: Ceramic
C8 = CMP-001-00003-15: Chip Capacitor, 1 uF, +/- 10%, 16 V, 0603 (1608 Metric); Capacitor Type: Ceramic; Decade: 1uF
C9 = CMP-001-00066-11: Chip Capacitor, 1nF +/-20%, 50V, 0402, Thickness 0.33 mm; Capacitor Type: Ceramic
D1 = CMP-004-00082-5: Rectifier Diode, 1 Phase, 1 Element, 8A, 1600V V(RRM), Silicon, TO-252AA; Vf: 1.1V; IF Surge: 150A
K1 K2 = CMP-008-00006-7: 5kV SPDT High Voltage Relay
R51 = CMP-009-00846-5: Chip Resistor, 4.53k Ohm, +/- 1%, 0.1 W, -55 to 155 degC, 0603 (1608 Metric); Voltage Rating: 75V; Decade: 1k; Power: 100mW
R52 R55-R57 = CMP-009-00017-8: Chip Resistor, 10 KOhm, +/- 1%, 01 W, -55 to 155 degC, 0603 (1608 Metric); Voltage Rating: 50V; Power: 100mW
R53 = CMP-009-00007-7: as R3-R40 on sheet Mezzanine_Conn
R54 = CMP-009-00872-5: Chip Resistor, 8.45k Ohm, +/- 1%, 0.1 W, -55 to 155 degC, 0603 (1608 Metric); Voltage Rating: 75V; Decade: 1k; Power: 100mW
R99-R101 R103 = CMP-009-01712-3: Generic 1% 1 MOhm 0805 Resistor; Voltage Rating: 150V; Power: 0.125W
TP4 = CMP-002-00083-13: PC TEST POINT MINIATURE WHITE; Manufacturer: Keystone
U3 = CMP-014-00006-4: TLV2452A Dual 23-UA 220-KHZ Rail; Gain Bandwidth Product: 220kHz; Amplifier Type: GENERAL PURPOSE; Number of Channels: 2; Voltage Gain: 103dB; Input Bias Current: 5nA; Max Dual Supply Voltage: 3V; Output Current: 10mA; Max Power Dissipation: 710mW; Max Supply Voltage: 6V; Common Mode Rejection Ratio: 70dB; Min Supply Voltage: 2.7V; Input Offset Voltage (Vos): 1mV; Slew Rate: 0.11V/µs; Min Dual Supply Voltage: 1.35V; Nominal Supply Current: 84uA

## Sheet Relay_Driver.SchDoc: MARS2 - IPB - Relay Driver
size 431 x 279 mm; Organization: ORGANIZATION; Address1: APPLIED PHYSICS LAB; Address2: UNIVERSITY OF WASHINGTON; Address3: 1013 NE 40TH STREET; Address4: SEATTLE, WA 98105; Revision: -; SheetNumber: 17; SheetTotal: 23; ENG_APP_DATE: --/--/--; DSN_APP_DATE: --/--/--; CHK_APP_DATE: --/--/--
Used 8 times, as channels Designator/Interface Channel A/Contactor Driver, Designator/Interface Channel A/Contactor Driver, Designator/Interface Channel B/Contactor Driver, Designator/Interface Channel B/Contactor Driver, Designator/Interface Channel C/Contactor Driver, Designator/Interface Channel C/Contactor Driver, Designator/Interface Channel D/Contactor Driver, Designator/Interface Channel D/Contactor Driver. Parts and nets are listed once, with the designators drawn on the sheet.
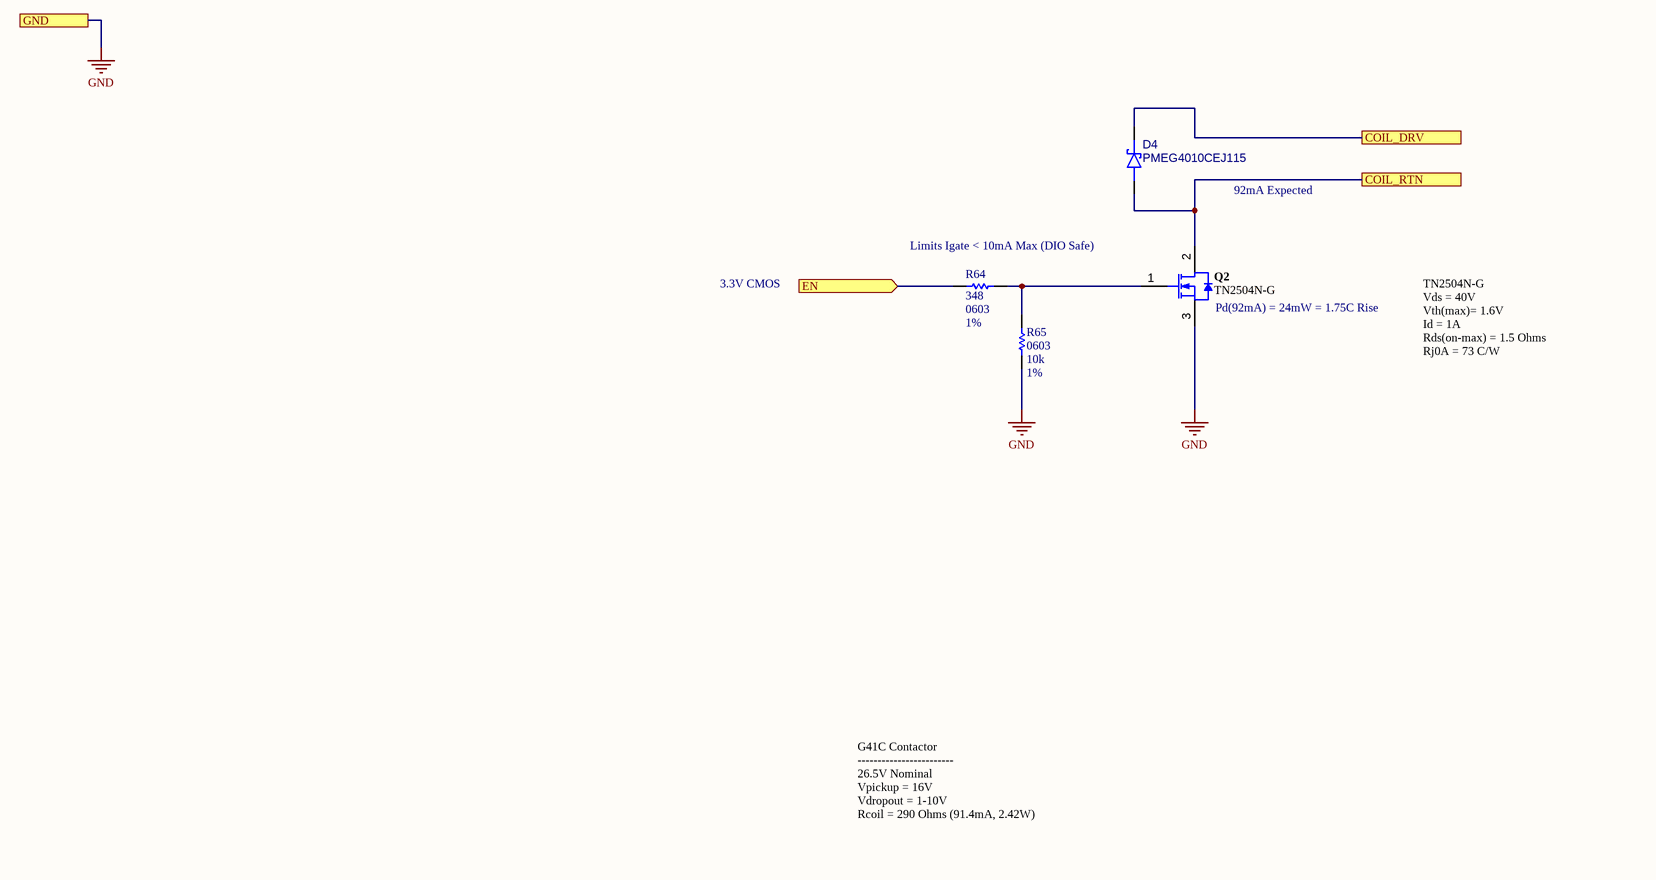
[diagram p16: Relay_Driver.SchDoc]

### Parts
D4  PMEG4010CEJ115  [SODFL250X80-2M]
Q2  TN2504N-G  [SOT89-150P341X160-3M]
R64  value 348  Case/Package: 0603  Tolerance: 1%  [RESC1609X50X30ML08T20]  (hidden comment: Resistor 348R +/-1% 0603 100 mW)
R65  value 10k  Case/Package: 0603  Tolerance: 1%  [RESC1608X55X25ML10T15]  (hidden comment: Resistor 10k +/-1% 0603 100 mW)

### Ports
COIL_DRV, COIL_RTN, EN (in), GND

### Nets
GND: Q2.3(S) R65.1 ; port GND
COIL_DRV: D4.1(K) ; port COIL_DRV
COIL_RTN: D4.2(A) Q2.2(D) ; port COIL_RTN
EN: R64.1 ; port EN
NetQ2_1: Q2.1(G) R64.2 R65.2

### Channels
Designator/Interface Channel A/Contactor Driver: designators end in _A; ports COIL_DRV=COIL_DRV_HIGH COIL_RTN=COIL_RTN_HIGH_Interface Channel A EN=CHA_RLY_EN GND=LV_GND
Designator/Interface Channel A/Contactor Driver: designators end in _B; ports COIL_DRV=COIL_DRV_HIGH COIL_RTN=COIL_RTN_LOW_Interface Channel A EN=CHA_RLY_EN GND=LV_GND
Designator/Interface Channel B/Contactor Driver: designators end in _C; ports COIL_DRV=COIL_DRV_HIGH COIL_RTN=COIL_RTN_HIGH_Interface Channel B EN=CHB_RLY_EN GND=LV_GND
Designator/Interface Channel B/Contactor Driver: designators end in _D; ports COIL_DRV=COIL_DRV_HIGH COIL_RTN=COIL_RTN_LOW_Interface Channel B EN=CHB_RLY_EN GND=LV_GND
Designator/Interface Channel C/Contactor Driver: designators end in _E; ports COIL_DRV=COIL_DRV_HIGH COIL_RTN=COIL_RTN_HIGH_Interface Channel C EN=CHC_RLY_EN GND=LV_GND
Designator/Interface Channel C/Contactor Driver: designators end in _F; ports COIL_DRV=COIL_DRV_HIGH COIL_RTN=COIL_RTN_LOW_Interface Channel C EN=CHC_RLY_EN GND=LV_GND
Designator/Interface Channel D/Contactor Driver: designators end in _G; ports COIL_DRV=COIL_DRV_HIGH COIL_RTN=COIL_RTN_HIGH_Interface Channel D EN=CHD_RLY_EN GND=LV_GND
Designator/Interface Channel D/Contactor Driver: designators end in _H; ports COIL_DRV=COIL_DRV_HIGH COIL_RTN=COIL_RTN_LOW_Interface Channel D EN=CHD_RLY_EN GND=LV_GND

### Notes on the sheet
- 92mA Expected
- (near R64) Limits Igate < 10mA Max (DIO Safe)
- 3.3V CMOS
- (near Q2) Pd(92mA) = 24mW = 1.75C Rise
- TN2504N-G
  Vds = 40V
  Vth(max)= 1.6V
  Id = 1A
  Rds(on-max) = 1.5 Ohms
  Rj0A = 73 C/W
- G41C Contactor
  ------------------------
  26.5V Nominal
  Vpickup = 16V
  Vdropout = 1-10V
  Rcoil = 290 Ohms (91.4mA, 2.42W)

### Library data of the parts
D4 = CMP-004-00035-1: NXP         PMEG4010CEJ,115            Schottky Rectifier, Single, 40 V, 1 A, SOD-323F, 2 Pins, 570 mV; Max Reverse Current: 50uA; Voltage: 40V; Max Power Dissipation: 830mW; Max Forward Surge Current (Ifsm): 10A; Forward Current: 1A
Q2 = CMP-013-00045-4: Transistor MOSFET N-CH 40V 0.89A 4-Pin (3+Tab) SOT-89; Max Power Dissipation: 1.6W; Gate to Source Voltage (Vgs): 20V; Polarity: N-CHANNEL; Continuous Drain Current (ID): 890mA
R64 = CMP-009-00745-5: Chip Resistor, 348 Ohm, +/- 1%, 0.1 W, -55 to 155 degC, 0603 (1608 Metric); Decade: 100; Power: 100mW; Voltage Rating: 75V
R65 = CMP-009-00017-8: as R52 on sheet Interface_Channel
